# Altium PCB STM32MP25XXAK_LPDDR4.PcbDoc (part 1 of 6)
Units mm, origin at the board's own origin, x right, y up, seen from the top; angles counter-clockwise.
Board outline 120 x 79.6 mm, 4 copper layers (Top Layer, Signal Layer 1, Signal Layer 2, Bottom Layer), stack 1.614 mm thick; 190 components, 143 nets, 1208 pads, 757 vias.
Unrouted connection lines stored in the file: 3.
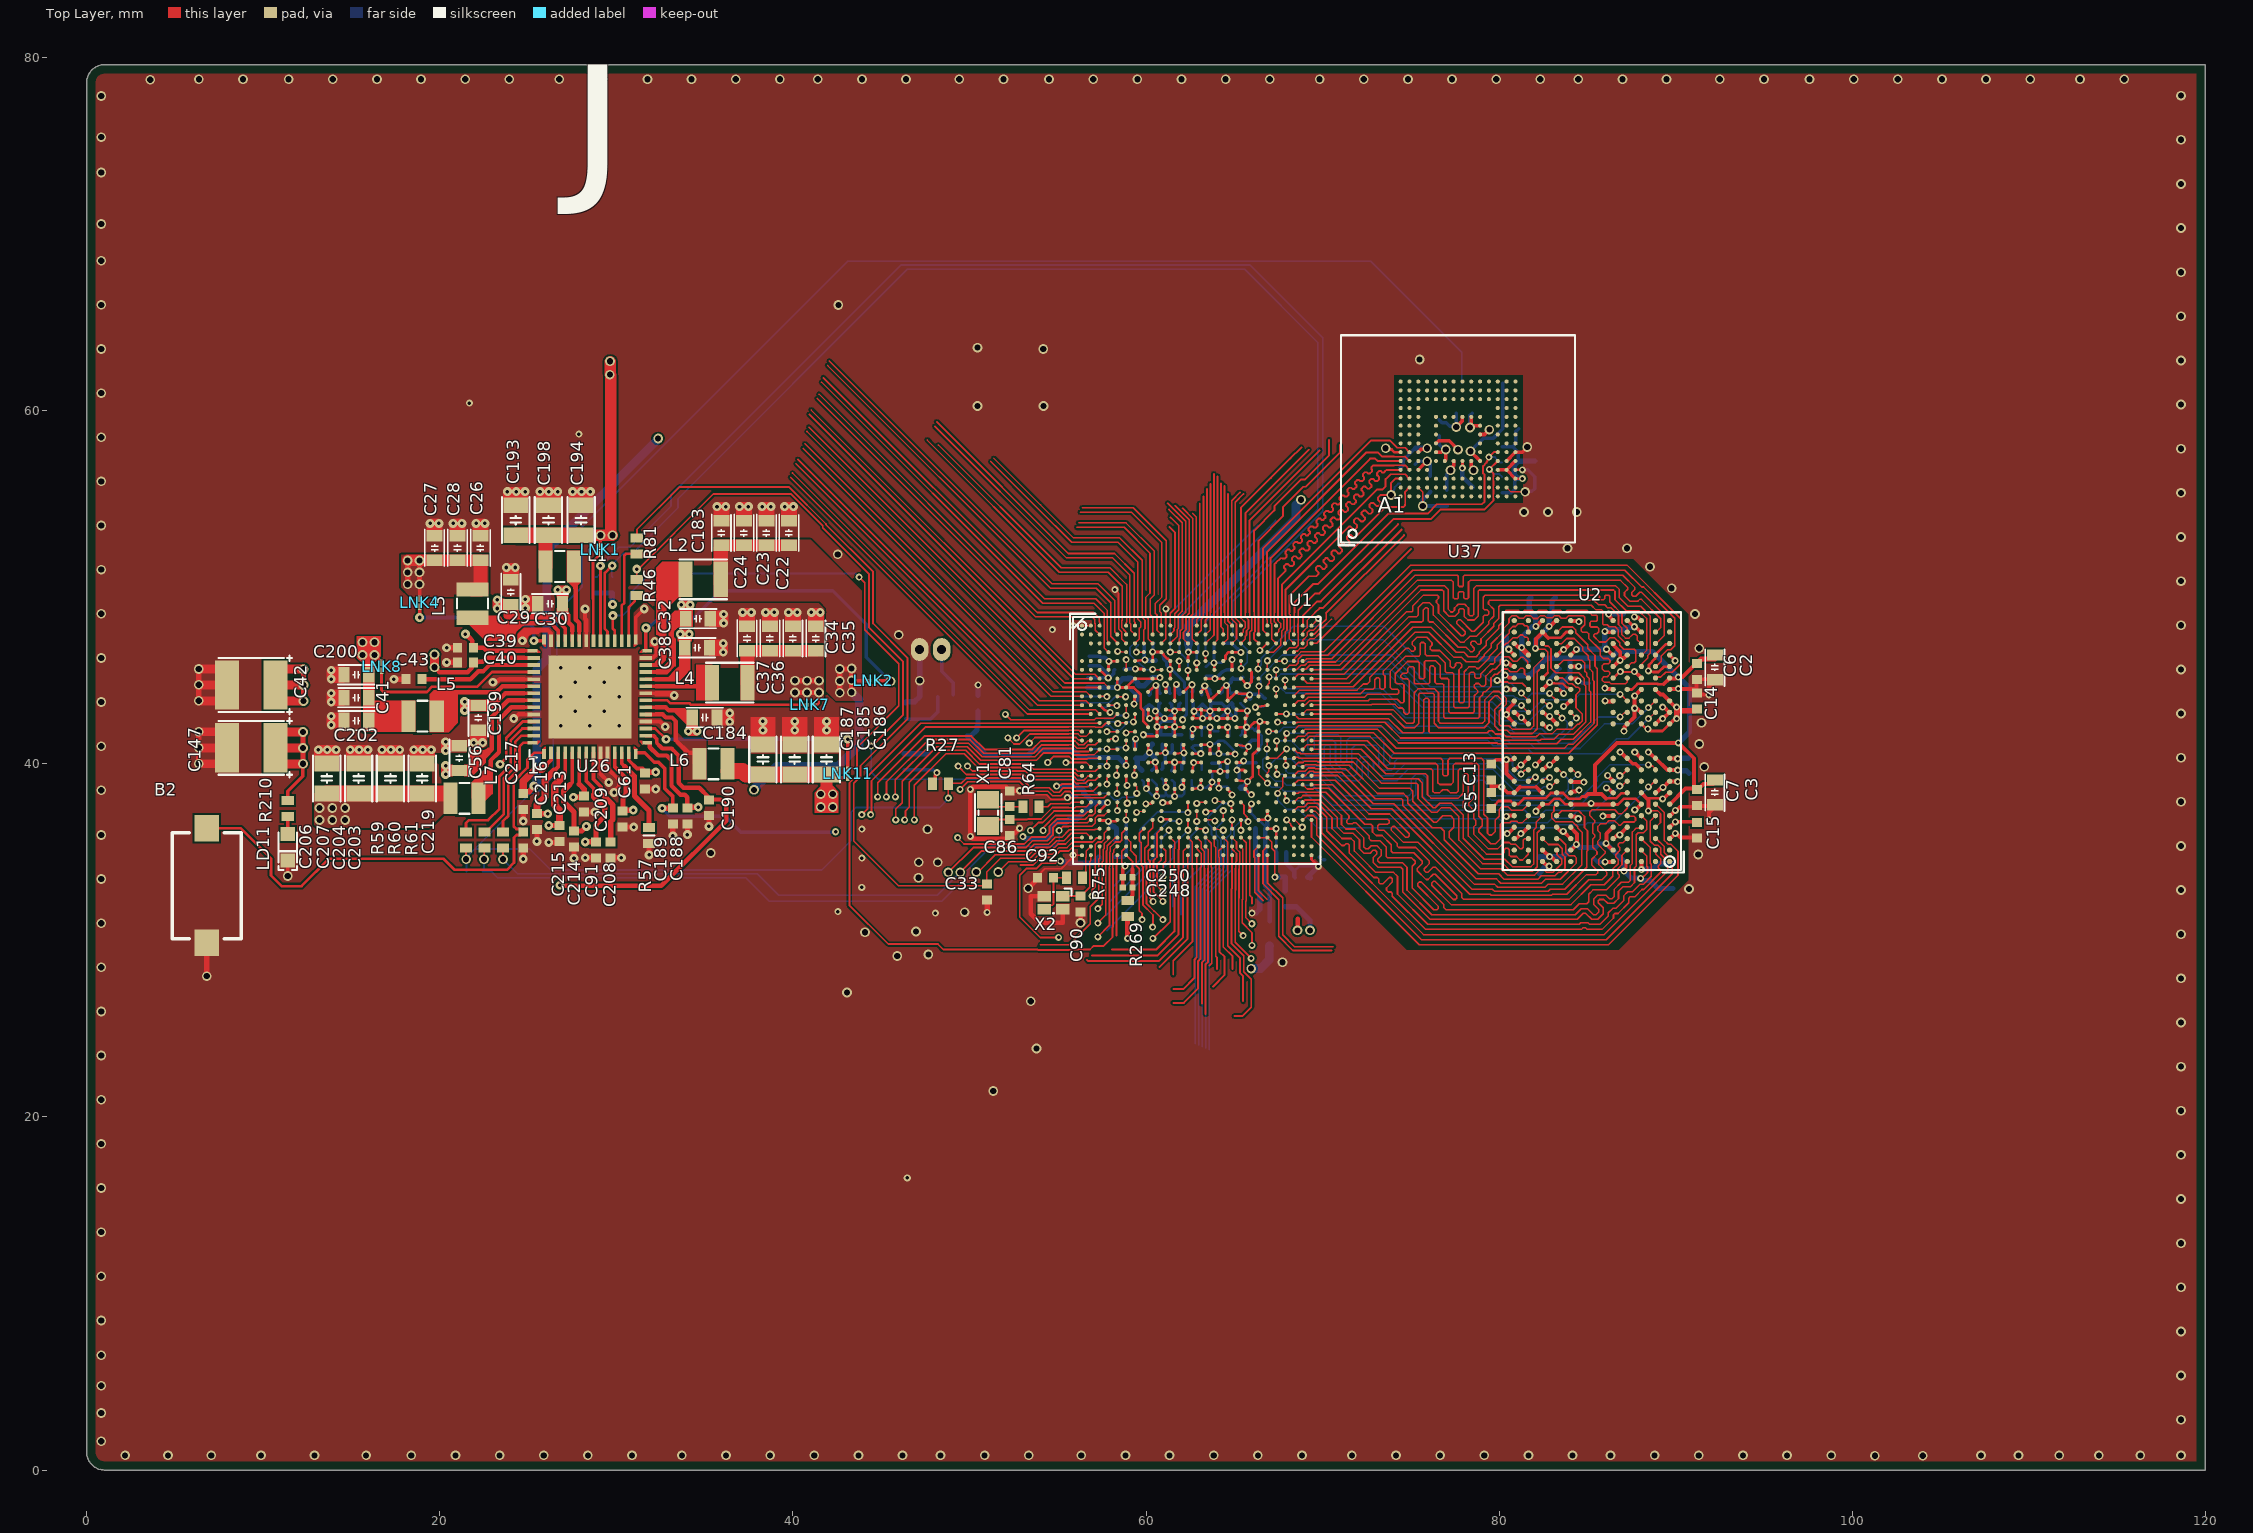
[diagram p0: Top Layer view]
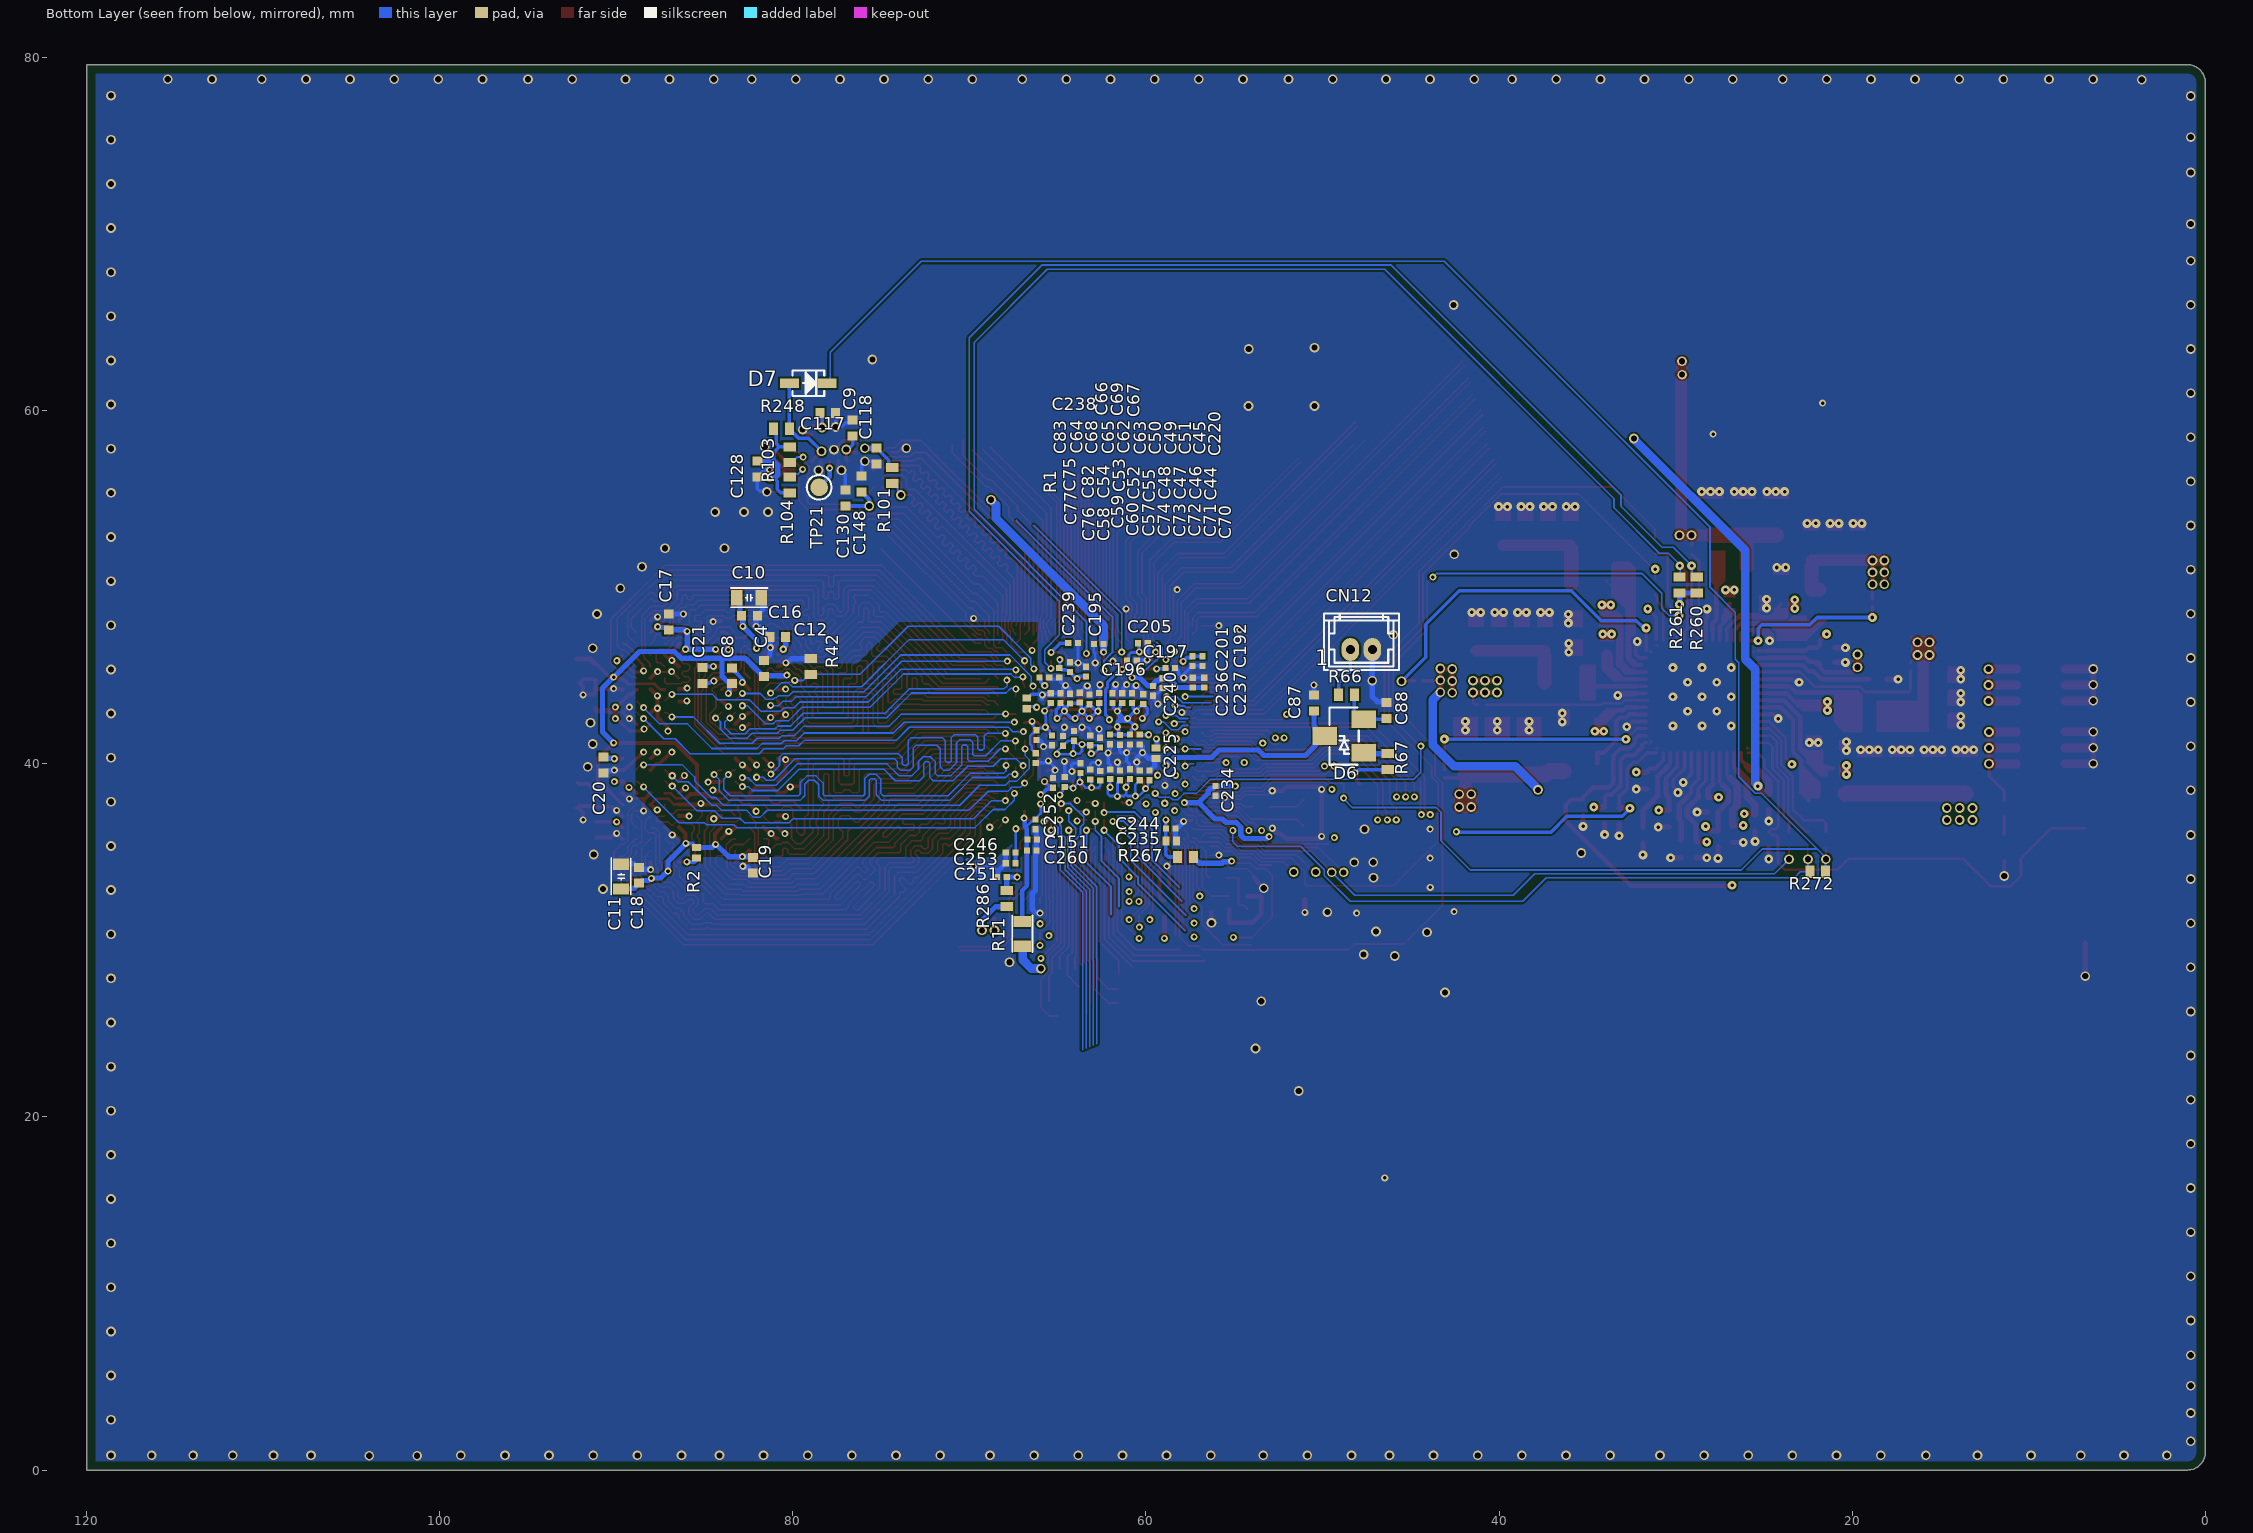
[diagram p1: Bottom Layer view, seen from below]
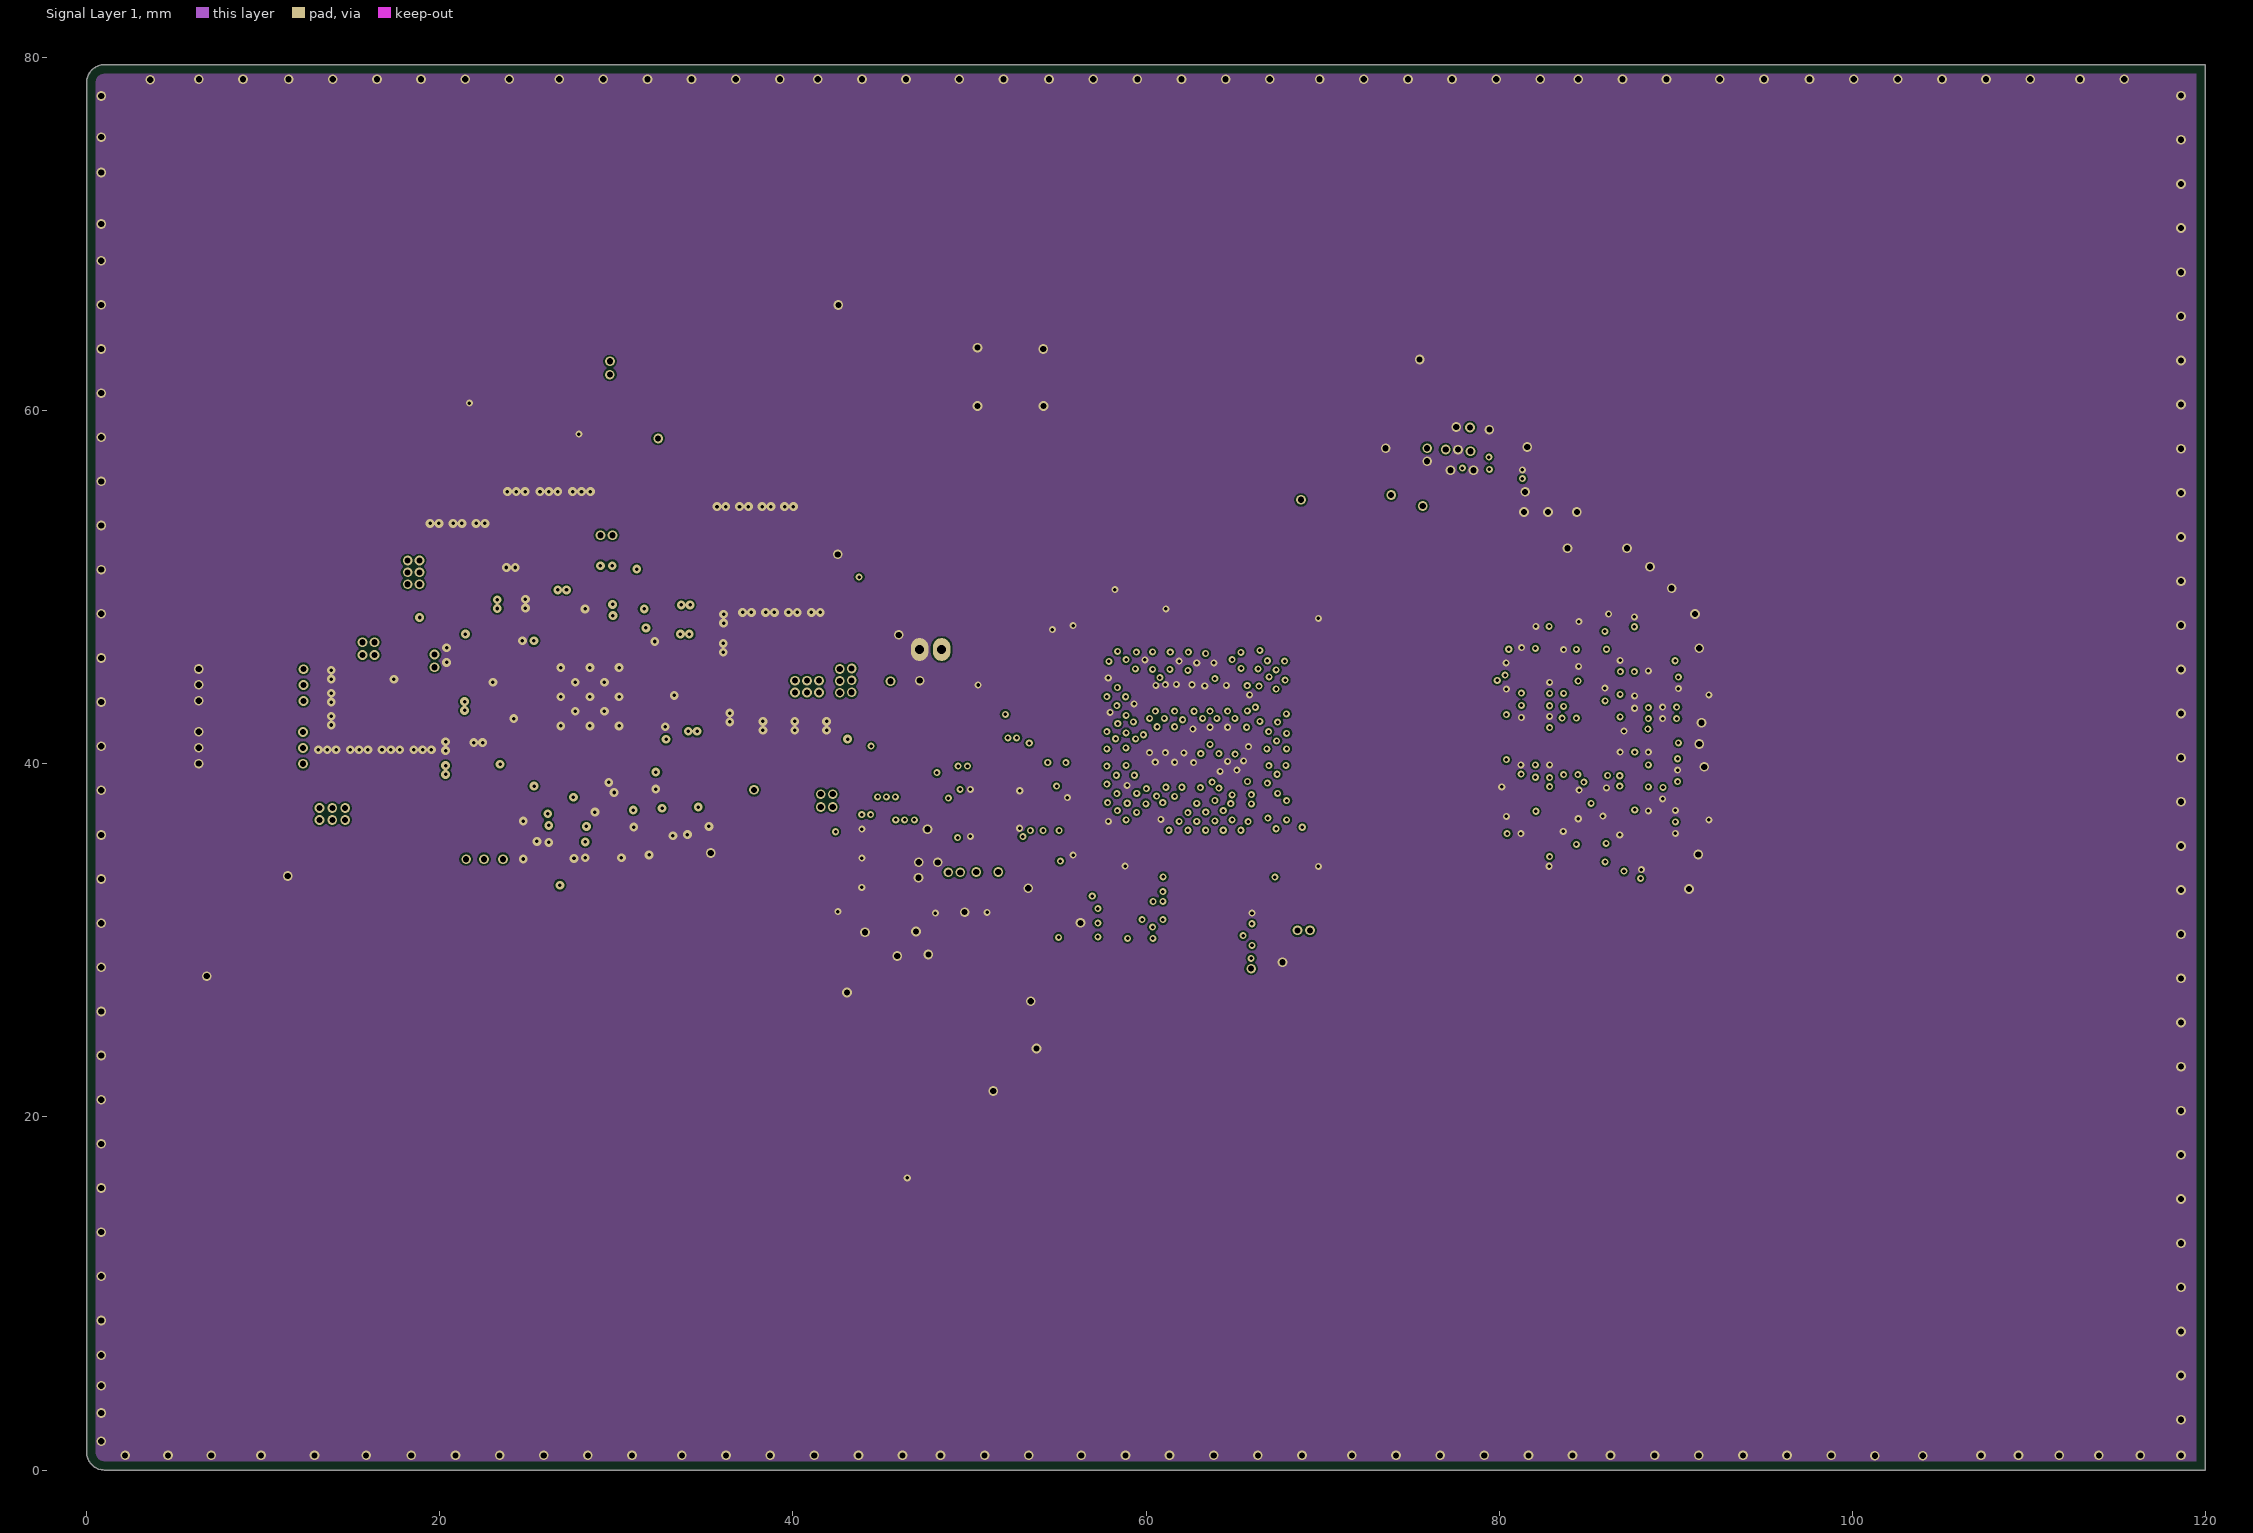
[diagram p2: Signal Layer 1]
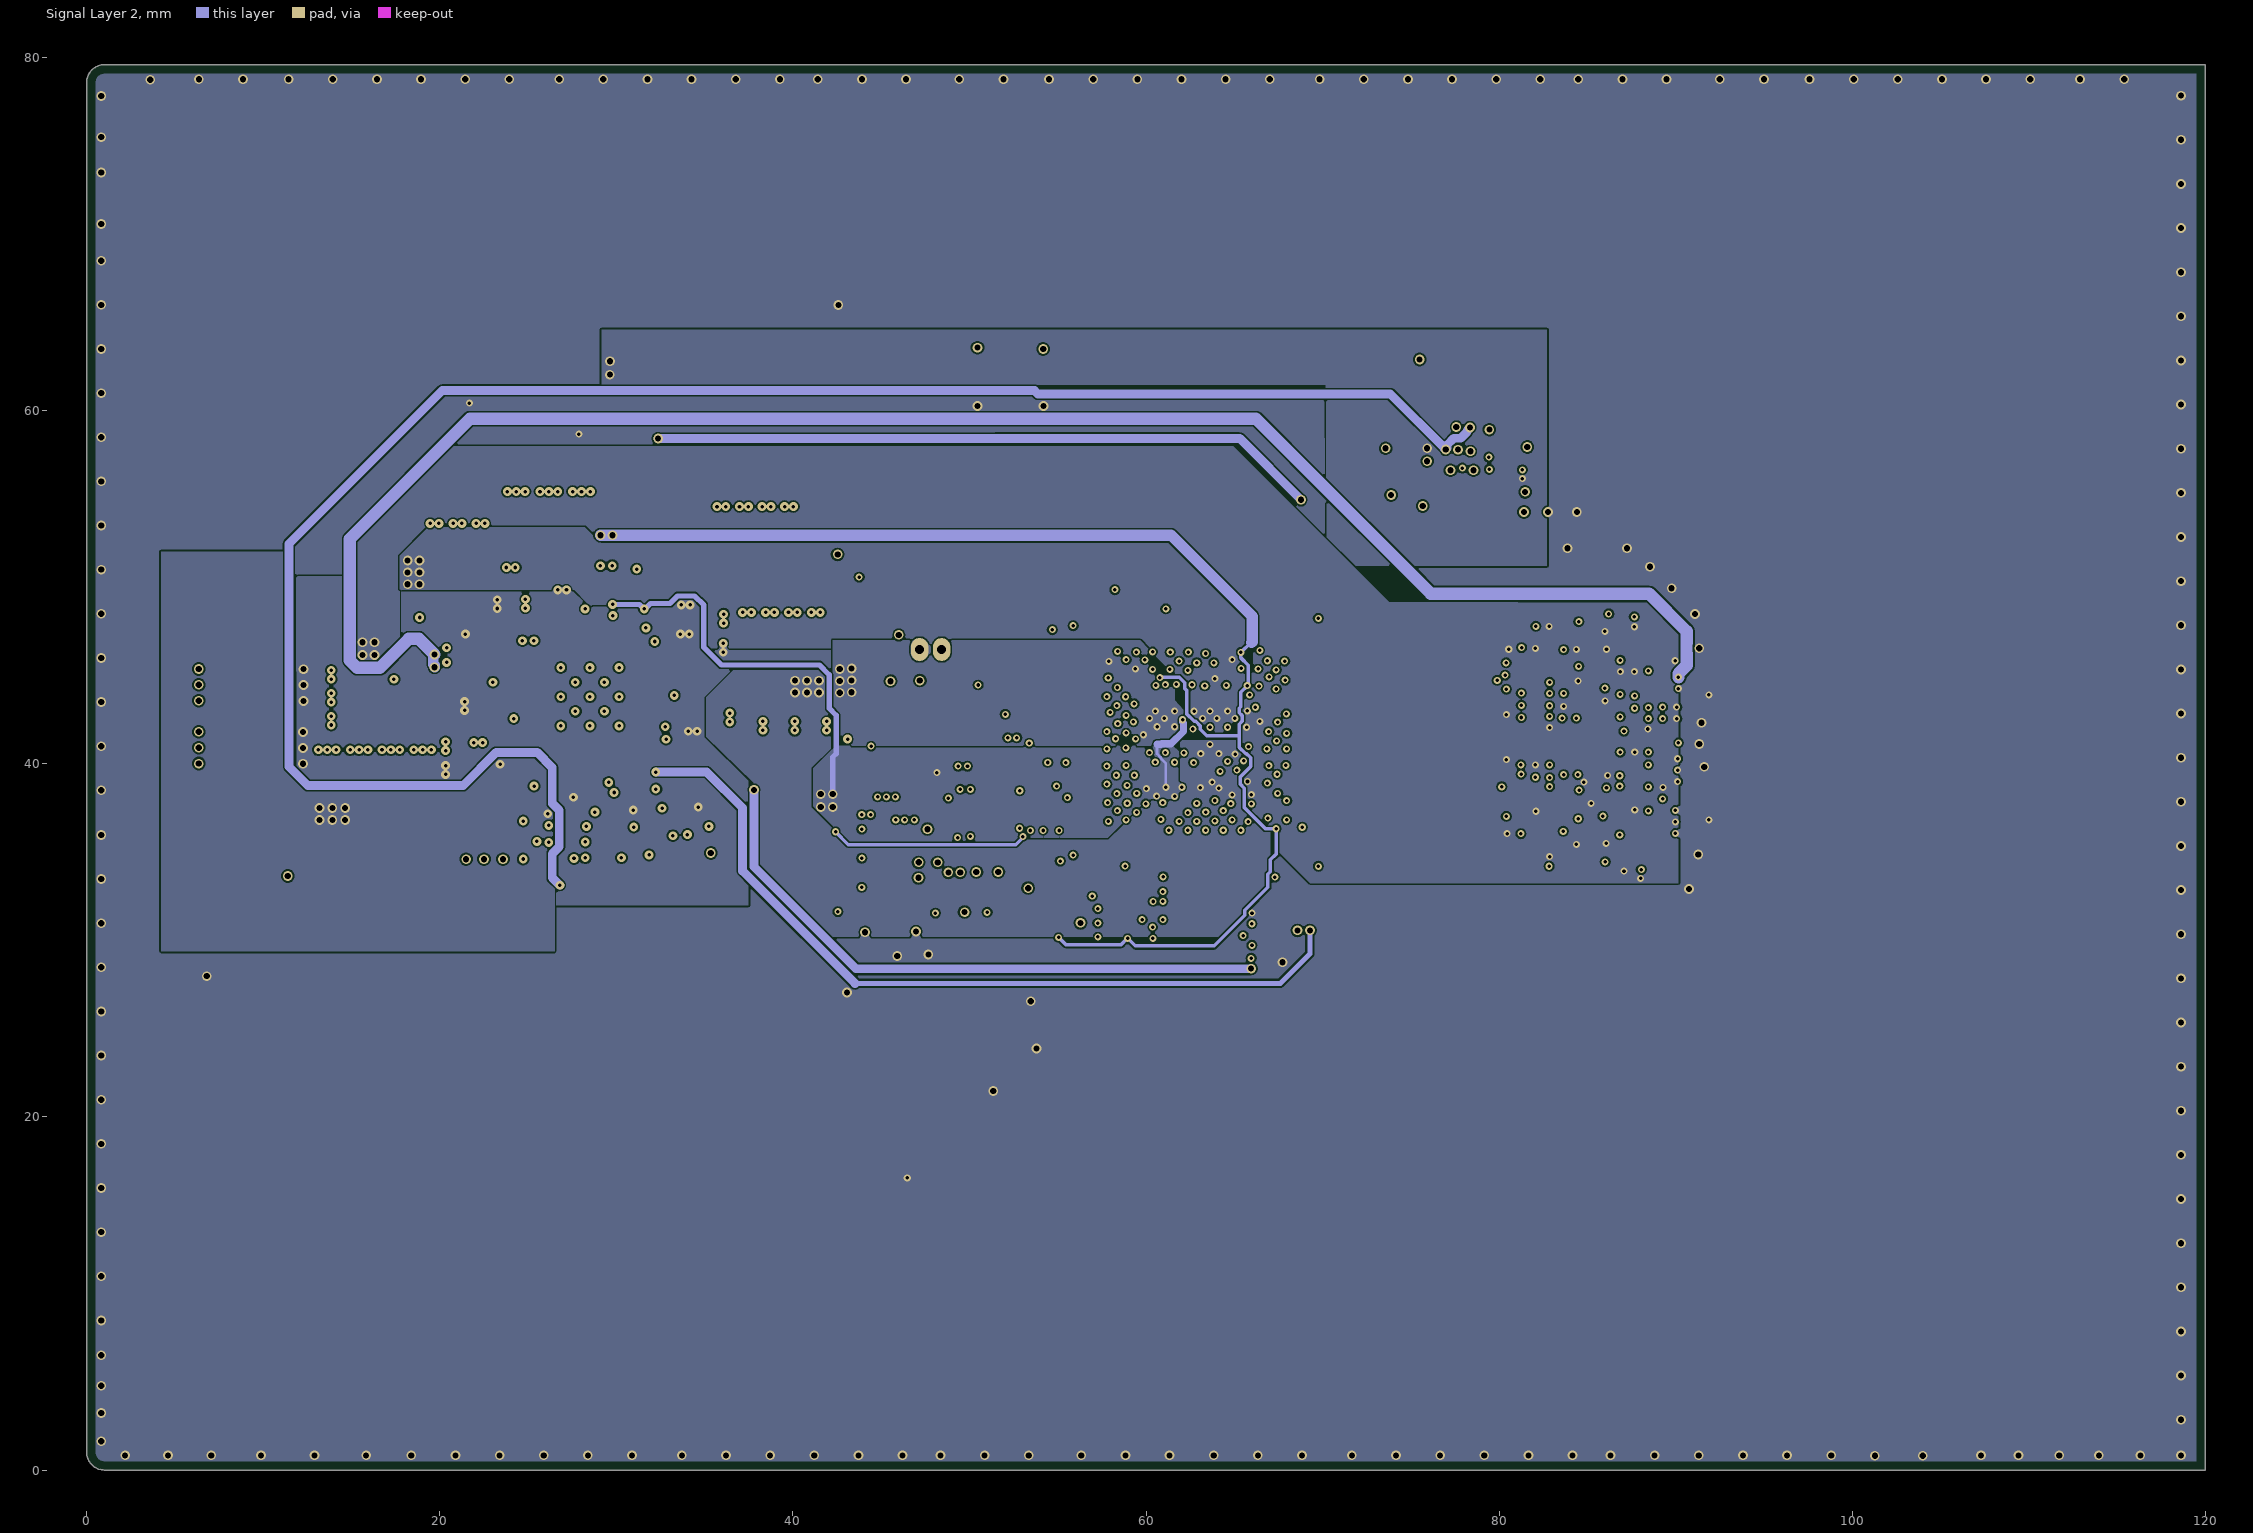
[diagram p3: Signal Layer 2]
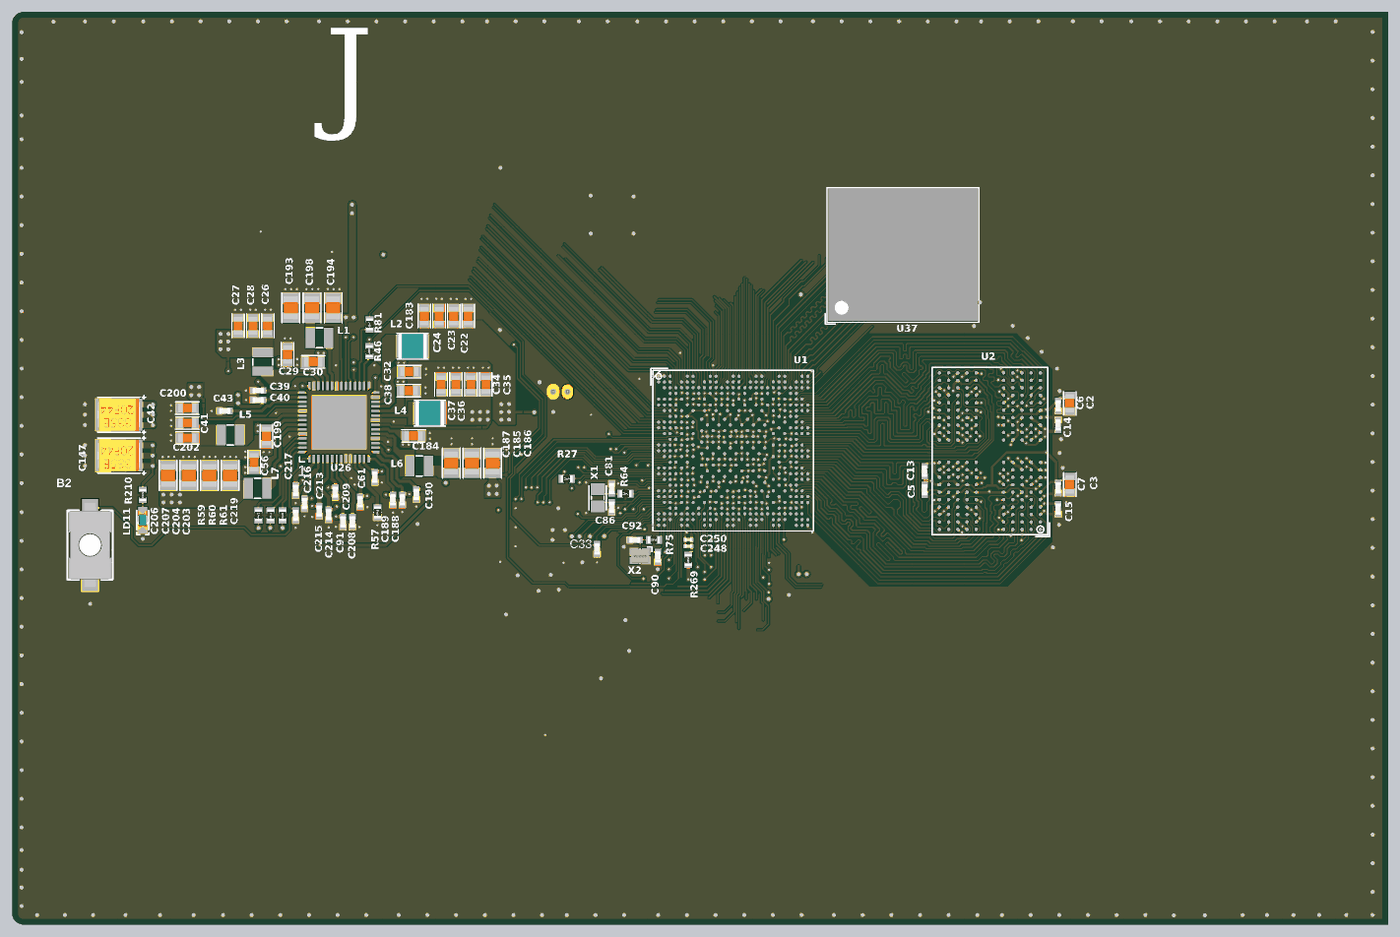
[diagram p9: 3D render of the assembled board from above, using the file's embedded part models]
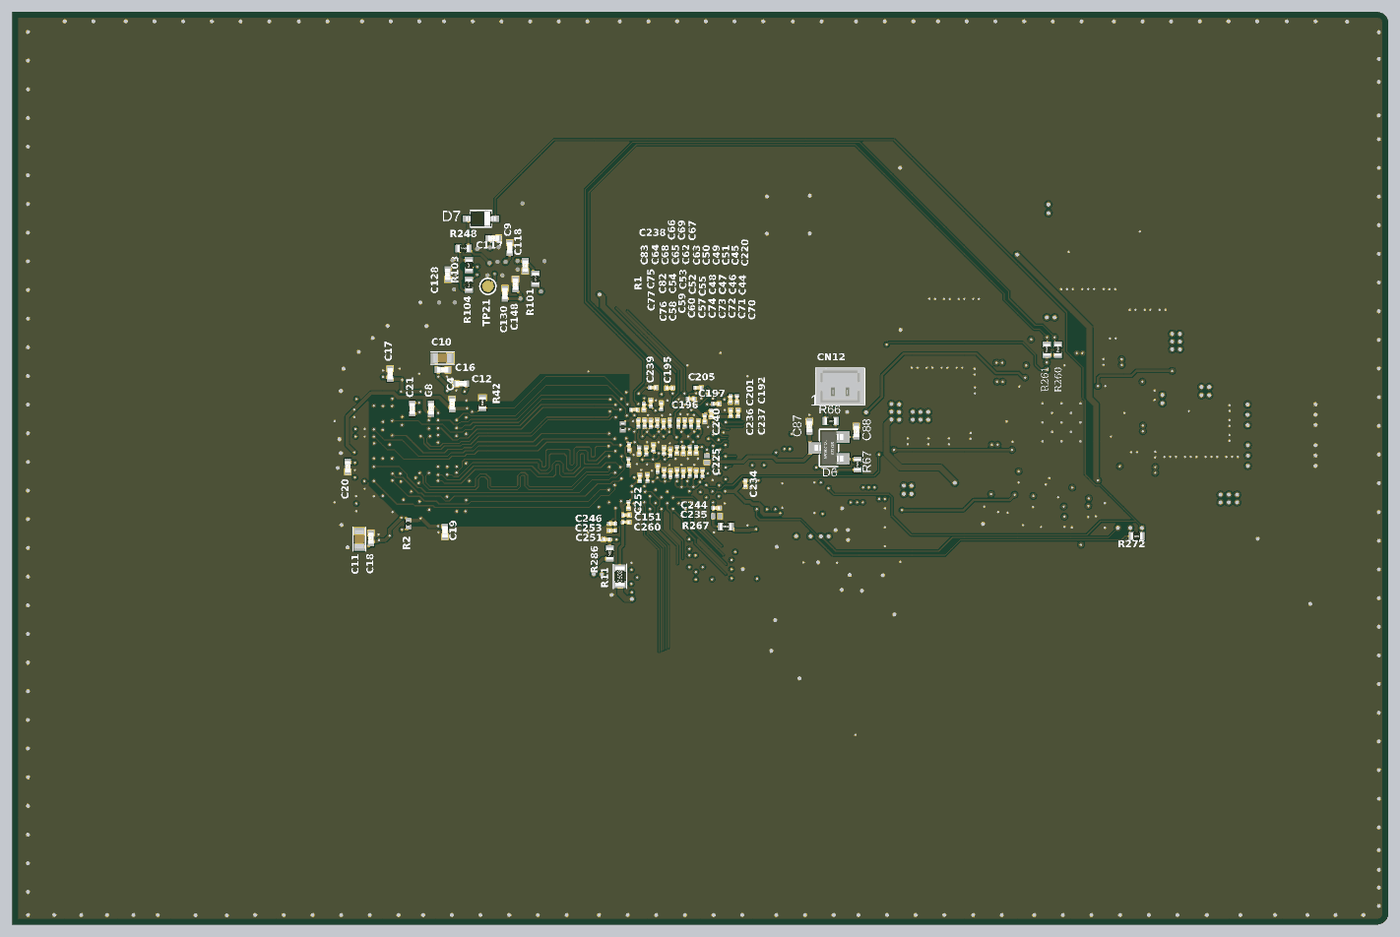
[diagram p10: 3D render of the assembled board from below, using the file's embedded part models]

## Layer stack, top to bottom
Top Solder: solder mask 0.025, Solder Resist, Dk 3.5
Top Layer: signal copper 0.037
Dielectric 1: prepreg 0.07, Dk 3.8
Signal Layer 1: signal copper 0.035
Dielectric 2: core 1.33, Dk 4.3
Signal Layer 2: signal copper 0.035
Dielectric 3: prepreg 0.07, Dk 3.8
Bottom Layer: signal copper 0.037
Bottom Solder: solder mask 0.025, Solder Resist, Dk 3.5

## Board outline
0,1 0,78.6 cw(c1,78.6) 1,79.6 120,79.6 120,0 1,0 cw(c1,1)

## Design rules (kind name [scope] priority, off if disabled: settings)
BoardOutlineClearance Silkscreen [OnLayer('Top Overlay') or OnLayer('Bottom Overlay')] p1: gap=0 ignorepadtopadclearanceinfootprint=FALSE
BoardOutlineClearance [All] p2: gap=0.5 ignorepadtopadclearanceinfootprint=FALSE
Clearance Clearance_Default [All] p1: gap=0.1 ignorepadtopadclearanceinfootprint=TRUE except(0: SMDPad-Hole Via-Hole; 0.09: Track-Track Track-SMDPad; 0.2: Arc-Hole Track-Hole THPad-Hole Fill-Hole Poly-Hole Region-Hole Text-Hole)
ComponentClearance [All] p1: gap=0.2 collisioncheckmode=3 verticalgap=0 showdistances=FALSE
DiffPairsRouting 100H [InDifferentialPairClass('100H')] p1: maxlimit=0.254 minlimit=0.16 mostfreqgap=0.16 toplayer_maxgap=0.16 toplayer_minwidth=0.09 toplayer_maxwidth=0.09 toplayer_prefwidth=0.09 midlayer1_minwidth=0.09 midlayer1_maxwidth=0.381 midlayer1_prefwidth=0.09 midlayer4_minwidth=0.09 midlayer4_maxwidth=0.381 midlayer4_prefwidth=0.09 bottomlayer_maxgap=0.16 bottomlayer_minwidth=0.09 bottomlayer_maxwidth=0.09 bottomlayer_prefwidth=0.09 impedanceprofiledriven=TRUE impedanceprofileid={628B3294-B84C-4222-8D8D-B3EA8745C43E} impedanceprofilevalue=100.000000 maxuncoupledlength=12.7
FanoutControl Fanout_BGA [IsBGA] p1: bgadir=Out bgaviamode=Closest fanoutstyle=Auto fanoutdirection=Alternating viagrid=0.025 // Fanout_BGA (Default Rule)
FanoutControl Fanout_LCC [IsLCC] p2: bgadir=Out bgaviamode=Closest fanoutstyle=Auto fanoutdirection=Alternating viagrid=0.025 // Fanout_LCC (Default Rule)
FanoutControl Fanout_SOIC [IsSOIC] p3: bgadir=Out bgaviamode=Closest fanoutstyle=Auto fanoutdirection=Alternating viagrid=0.025 // Fanout_SOIC (Default Rule)
FanoutControl Fanout_Small [(CompPinCount < 5)] p4: bgadir=Out bgaviamode=Closest fanoutstyle=Auto fanoutdirection=OutThenIn viagrid=0.025 // Fanout_Small (Default Rule)
FanoutControl Fanout_Default [All] p5: bgadir=Out bgaviamode=Closest fanoutstyle=Auto fanoutdirection=Alternating viagrid=0.025 // Fanout_Default (Default Rule)
HoleSize [All] p1: absolutevalues=TRUE maxlimit=10 minlimit=0.1 maxpercent=80.000 minpercent=20.000
HoleToHoleClearance [All] p1: gap=0.25 allowstackedmicrovias=TRUE
MinimumSolderMaskSliver MinimumSolderMaskSliver_SOLDER_BRIDGE [All vs HasFootprint('SOLDER-BRIDGE_R0603-0R')] p1: minsoldermaskwidth=0.07
MinimumSolderMaskSliver [All] p2: minsoldermaskwidth=0.075
NetAntennae [All] p1 off: netantennaetolerance=0
PlaneConnect [All] p1: planeconnectstyle=Direct reliefexpansion=0.508 reliefentries=4 reliefconductorwidth=0.21 reliefairgap=0.21
PolygonConnect PolygonConnect_Default [All] p1: connectstyle=Direct reliefconductorwidth=0.25 reliefentries=4 polygonreliefangle="90 Angle" airgapwidth=0.25
RoomDefinition RoomDefinition_eMMC [False] p1: confinementstyle=ConfineIn formatcopy=TRUE lockcomponents=FALSE outline 74.056,62.109 81.346,62.109 81.346,54.705 74.056,54.705
RoomDefinition RoomDefinition_DDR [False] p2: confinementstyle=ConfineIn formatcopy=TRUE lockcomponents=FALSE outline 79.028,49.26 90.8,49.26 90.8,33.46 79.028,33.46
RoomDefinition U_PMIC [InComponentClass('U_PMIC')] p3: confinementstyle=ConfineIn formatcopy=TRUE lockcomponents=FALSE outline 55.625,48.575 70.125,48.575 70.125,34.075 55.625,34.075
RoutingVias RoutingVias_Default [InDrillLayerPair('Top Layer - Bottom Layer')] p1: holewidth=0.15 width=0.4 viastyle="Through Hole" minholewidth=0.15 minwidth=0.4 maxholewidth=0.35 maxwidth=0.6 useviatemplates=TRUE viatemplateguid#1={8082EAB8-D593-4669-9C8E-234CD125C595} viatemplateguid#2={6F43EA8F-9356-47F3-9E64-8437B01C3073} viatemplateguid#3={0C56A9B8-CF93-463B-97D5-BDCC265789B0} viatemplateguid#4={9F28DA9E-6088-4B56-A5CF-E6C86A3E97F7} viatemplatename#1=v40h20m0mx0 viatemplatename#2=v40h20m25 viatemplatename#3=v50h20m25 viatemplatename#4=v55h35m40mx40
SilkToSilkClearance [All] p1: silktosilkclearance=0.2
SilkToSolderMaskClearance [IsPad] p1: minsilkscreentomaskgap=0.015 clearancetoexposedcopper=TRUE
SolderMaskExpansion [All] p1: expansion=0.1 istentingtop=FALSE
UnRoutedNet [All] p1 off:
ViasUnderSMD [InPadClass('PC_VIAS-IN-PAD_OK')] p1: allowed=TRUE
Width Width_SINGLE_50R [InNetClass('50H')] p1 off: maxlimit=0.199 minlimit=0.078 preferedwidth=0.199 toplayer_minwidth=0.09 toplayer_maxwidth=0.11 toplayer_prefwidth=0.11 bottomlayer_minwidth=0.11 bottomlayer_maxwidth=0.11 bottomlayer_prefwidth=0.11 impedanceprofiledriven=TRUE impedanceprofileid={152E730A-FDA4-4006-BF82-0EE0D5C1A339} impedanceprofilevalue=50.000000 minimp=50.000000 maximp=50.000000 favimp=50.000000
Width Width_SINGLE_DDR_55R [InNetClass('55H')] p2 off: maxlimit=0.199 minlimit=0.078 preferedwidth=0.199 toplayer_minwidth=0.09 toplayer_maxwidth=0.09 toplayer_prefwidth=0.09 bottomlayer_minwidth=0.09 bottomlayer_maxwidth=0.09 bottomlayer_prefwidth=0.09 impedanceprofiledriven=TRUE impedanceprofileid={D5948A69-504E-4D29-B9E5-77B49DDD78E4} impedanceprofilevalue=55.000000 minimp=50.000000 maximp=50.000000 favimp=50.000000
Width Width_Default [InNet('GND')] p3: maxlimit=10 minlimit=0.09 preferedwidth=0.3 toplayer_prefwidth=0.09 bottomlayer_prefwidth=0.09 minimp=50.000000 maximp=50.000000 favimp=50.000000
15 further rules are at their usual default settings.

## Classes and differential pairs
net class 100H: DDR_CLK_A_N DDR_CLK_A_P DDR_CLK_B_N DDR_CLK_B_P DDR_DQS0_A_N DDR_DQS0_A_P DDR_DQS0_B_N DDR_DQS0_B_P DDR_DQS1_A_N DDR_DQS1_A_P DDR_DQS1_B_N DDR_DQS1_B_P
differential pair class 100H: CLKA CLKB DQS0A DQS0B DQS1A DQS1B
net class eMMC.SDMMC2_D[0..7]: eMMC.SDMMC2_CK eMMC.SDMMC2_CMD eMMC.SDMMC2_D0 eMMC.SDMMC2_D1 eMMC.SDMMC2_D2 eMMC.SDMMC2_D3 eMMC.SDMMC2_D4 eMMC.SDMMC2_D5 eMMC.SDMMC2_D6 eMMC.SDMMC2_D7
component class U_eMMC: C9 C117 C118 C128 C130 C148 D7 R101 R103 R104 R248 TP21 U37
component class "U_STM32MP25XXAK I_Os": C33 C81 C86 C90 C92 R27 R64 R75 R260 R261 R272 U1 X1 X2
component class "U_STM32MP25XXAK Power": C44 C45 C46 C47 C48 C49 C50 C51 C52 C53 C54 C55 C57 C58 C59 C60 C62 C63 C64 C65 C66 C67 C68 C69 C70 C71 C72 C73 C74 C75 C76 C77 C82 C83 C87 C88 C151 C192 C195 C196 C197 C201 C205 C220 C225 C234 C235 C236 C237 C238 C239 C240 C244 C246 C248 C250 C251 C252 C253 C260 CN12 D6 R11 R66 R67 R267 R269 R286
component class U_PMIC: B2 C22 C23 C24 C26 C27 C28 C29 C30 C32 C34 C35 C36 C37 C38 C39 C40 C41 C42 C43 C56 C61 C91 C147 C183 C184 C185 C186 C187 C188 C189 C190 C193 C194 C198 C199 C200 C202 C203 C204 C206 C207 C208 C209 C213 C214 C215 C216 C217 C219 L1 L2 L3 L4 L5 L6 L7 LD11 LNK1 LNK2 LNK4 LNK7 LNK8 LNK11 R46 R57 R59 R60 R61 R81 R210 U26
differential pair CLKB: +DDR_CLK_B_P -DDR_CLK_B_N
differential pair CLKA: +DDR_CLK_A_P -DDR_CLK_A_N
differential pair DQS1B: +DDR_DQS1_B_P -DDR_DQS1_B_N
differential pair DQS0B: +DDR_DQS0_B_P -DDR_DQS0_B_N
differential pair DQS1A: +DDR_DQS1_A_P -DDR_DQS1_A_N
differential pair DQS0A: +DDR_DQS0_A_P -DDR_DQS0_A_N

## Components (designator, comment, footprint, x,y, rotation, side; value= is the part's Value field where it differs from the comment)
B2 "SW_PUSH_SMD_2P" SWI_WE_434121025816 6.795,33.104 r90 top value=434121025816
C2 "Capacitor" C0603 92.225,45.46 r90 top value=10uF
C3 "Capacitor" C0603 92.225,38.385 r90 top value=10uF
C4 "100nF" C0402 81.63,45.397 r90 bottom
C5 "100nF" C0402 79.559,37.929 r90 top
C6 "100nF" C0402 91.209,45.24 r270 top
C7 "100nF" C0402 91.209,38.09 r270 top
C8 "100nF" C0402 83.461,44.99 r90 bottom
C9 "Capacitor" C0402 76.615,59.03 r270 bottom value=100nF
C10 "Capacitor" C0603 82.486,49.415 r0 bottom value=10uF
C11 "Capacitor" C0603 89.736,33.615 r270 bottom value=10uF
C12 "100nF" C0402 80.861,47.18 r0 bottom
C13 "100nF" C0402 79.559,39.529 r270 top
C14 "100nF" C0402 91.209,43.565 r90 top
C15 "100nF" C0402 91.209,36.24 r270 top
C16 "100nF" C0402 82.461,48.39 r180 bottom
C17 "100nF" C0402 87.036,48.04 r90 bottom
C18 "100nF" C0402 88.711,33.69 r90 bottom
C19 "100nF" C0402 82.261,34.255 r270 bottom
C20 "100nF" C0402 90.736,39.94 r270 bottom
C21 "100nF" C0402 85.111,45.015 r90 bottom
C22 "Capacitor" C0603 39.775,53.075 r270 top value=22uF
C23 "Capacitor" C0603 38.5,53.075 r270 top value=22uF
C24 "Capacitor" C0603 37.225,53.075 r270 top value=22uF
C26 "Capacitor" C0603 22.3,52.225 r270 top value=22uF
C27 "Capacitor" C0603 19.7,52.225 r270 top value=22uF
C28 "Capacitor" C0603 21,52.225 r270 top value=22uF
C29 "Capacitor" C0603 24.025,49.725 r270 top value=10uF
C30 "Capacitor" C0603 26.25,49.075 r0 top value=10uF
C32 "Capacitor" C0603 34.625,48.225 r180 top value=10uF
C33 "Capacitor" C0402 51,32.75 r90 top value=10nF
C34 "Capacitor" C0603 40,47.1 r270 top value=22uF
C35 "Capacitor" C0603 41.3,47.1 r270 top value=22uF
C36 "Capacitor" C0603 38.7,47.1 r270 top value=22uF
C37 "Capacitor" C0603 37.4,47.1 r270 top value=22uF
C38 "Capacitor" C0603 34.575,46.575 r180 top value=10uF
C39 "Capacitor" C0402 21.445,46.575 r0 top value=1uF
C40 "Capacitor" C0402 21.445,45.75 r0 top value=10uF
C41 "Capacitor" C0603 15.275,43.75 r0 top value=22uF
C42 "Cap_POL_TANA" CPOL_TCJ-B_1210_H210 9.311,44.468 r180 top value=100uF
C43 "Capacitor" C0402 18.535,44.8 r0 top value=1uF
C44 "1uF" C0201_MURATA_GRM033_H0P3 60.351,41.38 r270 bottom
C45 "1uF" C0201_MURATA_GRM033_H0P3 60.16,43.67 r270 bottom
C46 "1uF" C0201_MURATA_GRM033_H0P3 60.915,41.38 r90 bottom
C47 "1uF" C0201_MURATA_GRM033_H0P3 61.476,41.356 r270 bottom
C48 "1uF" C0201_MURATA_GRM033_H0P3 62.038,41.382 r90 bottom
C49 "1uF" C0201_MURATA_GRM033_H0P3 61.35,43.725 r270 bottom
C50 "1uF" C0201_MURATA_GRM033_H0P3 61.9,43.725 r270 bottom
C51 "1uF" C0201_MURATA_GRM033_H0P3 60.8,43.725 r270 bottom
C52 "1uF" C0201_MURATA_GRM033_H0P3 63.162,41.332 r270 bottom
C53 "1uF" C0201_MURATA_GRM033_H0P3 64.083,41.581 r270 bottom
C54 "1uF" C0201_MURATA_GRM033_H0P3 64.706,41.304 r270 bottom
C55 "1uF" C0201_MURATA_GRM033_H0P3 62.6,41.2 r270 bottom
C56 "Capacitor" C0603 21.1,40.325 r270 top value=10uF
C57 "1uF" C0201_MURATA_GRM033_H0P3 62.592,39.328 r270 bottom
C58 "1uF" C0201_MURATA_GRM033_H0P3 64.607,38.972 r270 bottom
C59 "1uF" C0201_MURATA_GRM033_H0P3 63.714,39.761 r270 bottom
C60 "1uF" C0201_MURATA_GRM033_H0P3 63.154,39.397 r270 bottom
C61 "Capacitor" C0402 31.625,39.02 r90 top value=4.7uF
C62 "1uF" C0201_MURATA_GRM033_H0P3 63.2,43.65 r90 bottom
C63 "1uF" C0201_MURATA_GRM033_H0P3 62.65,43.73 r270 bottom
C64 "1uF" C0201_MURATA_GRM033_H0P3 64.85,43.725 r270 bottom
C65 "1uF" C0201_MURATA_GRM033_H0P3 63.75,43.75 r90 bottom
C66 "1uF" C0201_MURATA_GRM033_H0P3 64.915,45.16 r90 bottom
C67 "1uF" C0201_MURATA_GRM033_H0P3 63.4,45.225 r270 bottom
C68 "1uF" C0201_MURATA_GRM033_H0P3 64.3,43.7 r270 bottom
C69 "1uF" C0201_MURATA_GRM033_H0P3 64.305,45.477 r270 bottom
C70 "1uF" C0201_MURATA_GRM033_H0P3 59.805,39.35 r90 bottom
C71 "1uF" C0201_MURATA_GRM033_H0P3 60.355,39.35 r270 bottom
C72 "1uF" C0201_MURATA_GRM033_H0P3 60.905,39.423 r270 bottom
C73 "1uF" C0201_MURATA_GRM033_H0P3 61.467,39.349 r90 bottom
C74 "1uF" C0201_MURATA_GRM033_H0P3 62.03,39.408 r270 bottom
C75 "1uF" C0201_MURATA_GRM033_H0P3 66.205,41.625 r90 bottom
C76 "1uF" C0201_MURATA_GRM033_H0P3 65.274,38.923 r270 bottom
C77 "1uF" C0201_MURATA_GRM033_H0P3 66.25,40.325 r270 bottom
C81 "Capacitor" C0402 52.285,38.025 r90 top value=6.8pF
C82 "1uF" C0201_MURATA_GRM033_H0P3 65.325,41.325 r90 bottom
C83 "1uF" C0201_MURATA_GRM033_H0P3 65.395,43.725 r270 bottom
C86 "Capacitor" C0402 52.285,36.4 r270 top value=6.8pF
C87 "" C0402 50.485,43.438 r270 bottom value=100nF
C88 "Capacitor" C0402 46.382,43.015 r270 bottom value=2.2uF
C90 "Capacitor" C0402 56.293,32.06 r90 top value=6.8pF
C91 "Capacitor" C0402 28.85,35.13 r270 top value=4.7uF
C92 "Capacitor" C0402 54.309,33.546 r180 top value=6.8pF
C117 "Capacitor" C0402 78.025,59.864 r0 bottom value=2.2uF
C118 "Capacitor" C0402 75.26,57.43 r90 bottom value=100nF
C128 "Capacitor" C0402 82.015,56.705 r90 bottom value=2.2uF
C130 "Capacitor" C0402 77.027,55.055 r270 bottom value=100nF
C147 "Cap_POL_TANA" CPOL_TCJ-B_1210_H210 9.311,40.906 r180 top value=100uF
C148 "Capacitor" C0402 76.11,55.855 r270 bottom value=2.2uF
C151 "Capacitor" C0201_MURATA_GRM033_H0P3 66.446,35.716 r0 bottom value=1uF
C183 "Capacitor" C0603 35.95,53.075 r270 top value=22uF
C184 "Capacitor" C0603 34.997,42.625 r180 top value=10uF
C185 "Capacitor" C0805 40.1,40.25 r270 top value=22uF
C186 "Capacitor" C0805 41.9,40.25 r270 top value=22uF
C187 "Capacitor" C0805 38.3,40.25 r270 top value=22uF
C188 "Capacitor" C0402 34.025,37.04 r90 top value=1uF
C189 "Capacitor" C0402 33.2,37.04 r90 top value=4.7uF
C190 "Capacitor" C0402 35.25,37.515 r270 top value=4.7uF
C192 "Capacitor" C0201_MURATA_GRM033_H0P3 56.8,45.825 r90 bottom value=100nF
C193 "Capacitor" C0805 24.3,53.8 r270 top value=22uF
C194 "Capacitor" C0805 28,53.8 r270 top value=22uF
C195 "Capacitor" C0201_MURATA_GRM033_H0P3 62.675,46.787 r180 bottom value=100nF
C196 "Capacitor" C0201_MURATA_GRM033_H0P3 60.8,45.85 r0 bottom value=100nF
C197 "Capacitor" C0201_MURATA_GRM033_H0P3 58.625,45.425 r0 bottom value=100nF
C198 "Capacitor" C0805 26.15,53.8 r270 top value=22uF
C199 "Capacitor" C0603 22.175,42.6 r90 top value=10uF
C200 "Capacitor" C0603 15.275,45.05 r0 top value=22uF
C201 "Capacitor" C0201_MURATA_GRM033_H0P3 57.375,45.825 r90 bottom value=100nF
C202 "Capacitor" C0603 15.275,42.45 r0 top value=22uF
C203 "Capacitor" C0805 19,39.173 r270 top value=22uF
C204 "Capacitor" C0805 17.2,39.173 r270 top value=22uF
C205 "Capacitor" C0201_MURATA_GRM033_H0P3 60.177,46.829 r0 bottom value=100nF
C206 "Capacitor" C0805 13.6,39.173 r270 top value=22uF
C207 "Capacitor" C0805 15.4,39.173 r270 top value=22uF
C208 "Capacitor" C0402 29.675,35.13 r270 top value=4.7uF
C209 "Capacitor" C0402 30.35,36.87 r90 top value=4.7uF
C213 "Capacitor" C0402 28.175,37.72 r90 top value=1uF
C214 "Capacitor" C0402 27.6,35.75 r270 top value=4.7uF
C215 "Capacitor" C0402 26.775,36.06 r270 top value=4.7uF
C216 "Capacitor" C0402 25.5,36.725 r90 top value=1uF
C217 "Capacitor" C0402 24.725,37.87 r270 top value=4.7uF
C219 "Capacitor" C0402 24.727,35.695 r90 top value=10nF
C220 "Capacitor" C0201_MURATA_GRM033_H0P3 59.609,44.131 r90 bottom value=100nF
C225 "Capacitor" C0201_H0P5 59.425,40.6 r90 bottom value=4.7uF
C234 "Capacitor" C0201_MURATA_GRM033_H0P3 56.064,38.473 r90 bottom value=100nF
C235 "Capacitor" C0201_H0P5 58.575,35.625 r0 bottom value=2.2uF
C236 "Capacitor" C0201_MURATA_GRM033_H0P3 57.35,44.6 r270 bottom value=100nF
C237 "Capacitor" C0201_MURATA_GRM033_H0P3 56.696,44.605 r270 bottom value=100nF
C238 "Capacitor" C0201_MURATA_GRM033_H0P3 65.758,44.894 r0 bottom value=100nF
C239 "Capacitor" C0201_MURATA_GRM033_H0P3 64.125,46.837 r0 bottom value=100nF
C240 "Capacitor" C0201_MURATA_GRM033_H0P3 59.05,44.575 r90 bottom value=100nF
C244 "Capacitor" C0201_MURATA_GRM033_H0P3 58.6,36.331 r0 bottom value=100nF
C246 "Capacitor" C0201_MURATA_GRM033_H0P3 67.666,34.986 r180 bottom value=100nF
C248 "Capacitor" C0201_MURATA_GRM033_H0P3 58.958,33.002 r0 top value=100nF
C250 "Capacitor" C0201_MURATA_GRM033_H0P3 58.958,33.572 r0 top value=1uF
C251 "Capacitor" C0201_MURATA_GRM033_H0P3 68.165,33.588 r180 bottom value=100nF
C252 "Capacitor" C0201_MURATA_GRM033_H0P3 66.255,36.575 r90 bottom value=1uF
C253 "Capacitor" C0201_MURATA_GRM033_H0P3 67.666,34.367 r180 bottom value=100nF
C260 "Capacitor" C0201_MURATA_GRM033_H0P3 66.473,35.094 r0 bottom value=1uF
CN12 "" CON_MOLEX_53047-0210 47.8,46.475 r180 bottom value="Header 2x1"
D6 "DIODE_3P_DUAL_COMMON_CATHODE" DIO_SOT23 48.773,41.573 r90 bottom value=BAT54CFILM
D7 "BAT60JFILM" DIO_SOD323 79.125,61.563 r180 bottom
L1 "Inductor" IND_2016_MURATA_LQM2MPN2R2NG0 26.795,51.175 r180 top value=2.2uH
L2 "Inductor" IND_2520_TOKO_DFE252012P 34.915,50.45 r0 top value=0.68µH
L3 "Inductor" IND_2016_MURATA_LQM2MPN2R2NG0 21.85,49.075 r90 top value=0.68uH
L4 "Inductor" IND_2520_TOKO_DFE252012P 36.425,44.6 r0 top value=0.68µH
L5 "Inductor" IND_2016_MURATA_LQM2MPN2R2NG0 19.025,42.7 r180 top value=0.68uH
L6 "Inductor" IND_2016_MURATA_LQM2MPN2R2NG0 35.5,40 r0 top value=2.2uH
L7 "Inductor" IND_2016_MURATA_LQM2MPN2R2NG0 21.4,38.05 r180 top value=0.68uH
LD11 "LED_green" LED_0603_OSRAM_LG-Q396-PS-35_GREEN_1A2K_H0P4 11.386,35.272 r270 top value=GREEN
LNK1 "link_200" LINK200 29.1,52.123 r0 top
LNK2 "link_200" LINK200 44.541,44.7 r90 top
LNK4 "link_200" LINK200 18.85,49.125 r180 top
LNK7 "link_200" LINK200 40.95,43.35 r270 top
LNK8 "link_200" LINK200 16.7,45.498 r0 top
LNK11 "link_200" LINK200 43.1,39.44 r180 top
R1 "Resistor" R0201_H0P23 66.751,43.42 r270 bottom value=240R
R2 "Resistor" R0201_H0P23 85.461,34.965 r90 bottom value=240R
R11 "Resistor" R0603 67,30.375 r90 bottom value=0R
R27 "Resistor" R0402 48.355,38.872 r180 top value=10K
R42 "Resistor" R0402 78.986,45.505 r270 bottom value=10K
R46 "" R0402 31.15,49.998 r270 top value=0R
R57 "" R0402 31.85,35.95 r90 top value=0R
R59 "" R0402 21.48,35.695 r90 top value=0R
R60 "" R0402 22.53,35.695 r90 top value=0R
R61 "" R0402 23.58,35.695 r90 top value=0R
R64 "" R0402 53.485,37.575 r180 top value=0R
R66 "Resistor" R0402 48.633,43.917 r180 bottom value=20R
R67 "Resistor" R0402 46.3,40.125 r270 bottom value=0R
R75 "" R0402 55.959,33.546 r0 top value=0R
R81 "" R0402 31.163,52.348 r270 top value=0R
R101 "Resistor" R0402 74.375,56.325 r90 bottom value=10K
R103 "Resistor" R0402 80.171,57.511 r90 bottom value=10K
R104 "Resistor" R0402 80.175,55.805 r270 bottom value=10K
R210 "Resistor" R0402 11.386,37.465 r270 top value=270R
R248 "Resistor" R0402 80.657,58.98 r0 bottom value=10K
R260 "Resistor" R0402 28.805,50.13 r270 bottom value=1K5
R261 "Resistor" R0402 29.78,50.13 r270 bottom value=1K5
R267 "" R0402 57.773,34.723 r180 bottom value=0R
R269 "" R0402 58.956,31.808 r90 top value=0R
R272 "Resistor" R0402 21.95,33.879 r0 bottom value=10K
R286 "" R0402 67.89,32.365 r90 bottom value=0R
TP21 "Test Point" TP_SMD_1MM 78.516,55.665 r90 bottom
U1 "STM32MP257FAK3" ICC_TFBGA424_14X14_P050_H1P20_CODE-B0A2 62.875,41.325 r0 top locked
U2 "MT53E1G32D2FW-046 WT:C" ICC_TFBGA200_10X14P5_P080_H1P05_PS0P3 85.26,41.29 r180 top locked
U26 "STPMIC25APQR" ICC_QFN56-EPAD_6P5X6P5_P040 28.5,43.8 r90 top
U37 "eMMC_THGBMTG5D1LBAIL" ICC_P-WFBGA153_13X11P5_P050 77.675,58.405 r0 top locked value=THGBMTG5D1LBAIL
X1 "XTAL_2_PINS" CRY_NX2012SA_2P 51.059,37.225 r270 top value=32.768KHz
X2 "XTAL_4_PINS" CRY_NX1612SA_4P 54.759,32.135 r180 top value=40MHz

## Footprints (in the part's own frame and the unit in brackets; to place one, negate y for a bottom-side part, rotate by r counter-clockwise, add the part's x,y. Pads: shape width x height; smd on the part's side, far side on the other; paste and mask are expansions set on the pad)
C0201_H0P5 [mm] "MCD-01534"
  rect 0.4x0.5 smd mask+0.05: 1(-0.3,0) 2(0.3,0)
  body extent -0.35,-0.2 0.35,0.2, height 0.55
C0201_MURATA_GRM033_H0P3 [mm] "GRM033R60J105ME11"
  rect 0.35x0.35 smd mask+0.05: 1(-0.275,0) 2(0.275,0)
  body extent -0.32,-0.17 0.32,0.17, height 0.33
C0402 [mm]
  rect 0.51x0.56 smd mask+0.05: 1(-0.45,0) 2(0.45,0)
  body extent -0.5,-0.3 0.5,0.3, height 0.4
C0603 [mm]
  rect 0.64x0.89 smd mask+0.05: 1(-0.7,0) 2(0.7,0)
  silkscreen extent -1.05,-0.55 1.02,0.55, body extent -0.9,-0.5 0.9,0.5, height 1.4
C0805 [mm]
  rect 0.9x1.4 smd mask+0.05: 1(-0.85,0) 2(0.85,0)
  silkscreen extent -1.3,-0.77 1.3,0.77, body extent -1.1,-0.7 1.1,0.7, height 1.35
CON_MOLEX_53047-0210 [mm]
  oval 1x1.3 hole 0.5 mask+0.05: 1(-0.625,0) 2(0.625,0)
  silkscreen extent -2.12,-1.15 2.13,2.05, body extent -2.12,-1.15 2.13,2.05, height 4.2
CPOL_TCJ-B_1210_H210 [mm] "MCD-01791"
  rect 1.35x2.8 smd mask+0.05: 1(-1.375,0) 2(1.375,0)
  silkscreen extent -2.33,-1.68 1.85,1.68, body extent -1.85,-1.5 1.85,1.5, height 2.11
CRY_NX1612SA_4P [mm] "MCD-02262"
  rect 0.75x0.6 smd mask+0.038: 1(-0.525,-0.375) 2(0.525,-0.375) 3(0.525,0.375) 4(-0.525,0.375)
  silkscreen extent -1.02,-0.8 0.03,0.6, body extent -0.8,-0.6 0.8,0.6, height 0.51
CRY_NX2012SA_2P [mm]
  rect 1x1.25 smd mask+0.05: 1(-0.75,0) 2(0.75,0)
  silkscreen extent -1.05,-0.75 1.05,0.75, body extent -1.05,-0.63 1.05,0.63, height 0.6
DIO_SOD323 [mm]
  rect 1.06x0.54 smd mask+0.05: 1(-1.07,0) 2(1.07,0)
  silkscreen extent -0.9,-0.72 0.9,0.72, body extent -1.3,-0.78 1.3,0.78, height 1.17
DIO_SOT23 [mm]
  rect 1x1.4 smd mask+0.05: 1(-0.95,-1.1) 2(0.95,-1.1) 3(0,1.1)
  silkscreen extent -1.63,-0.82 1.63,0.82, body extent -1.56,-1.25 1.56,1.25, height 1.1
ICC_P-WFBGA153_13X11P5_P050 [mm]
  round 0.23 smd mask+0.05: A1(-3.25,-3.25) A2(-3.25,-2.75) A3(-3.25,-2.25) A4(-3.25,-1.75) A5(-3.25,-1.25) A6(-3.25,-0.75) A7(-3.25,-0.25) A8(-3.25,0.25) A9(-3.25,0.75) A10(-3.25,1.25) A11(-3.25,1.75) A12(-3.25,2.25) A13(-3.25,2.75) A14(-3.25,3.25) B1(-2.75,-3.25) B2(-2.75,-2.75) B3(-2.75,-2.25) B4(-2.75,-1.75) B5(-2.75,-1.25) B6(-2.75,-0.75) B7(-2.75,-0.25) B8(-2.75,0.25) B9(-2.75,0.75) B10(-2.75,1.25) B11(-2.75,1.75) B12(-2.75,2.25) B13(-2.75,2.75) B14(-2.75,3.25) C1(-2.25,-3.25) C2(-2.25,-2.75) C3(-2.25,-2.25) C4(-2.25,-1.75) C5(-2.25,-1.25) C6(-2.25,-0.75) C7(-2.25,-0.25) C8(-2.25,0.25) C9(-2.25,0.75) C10(-2.25,1.25) C11(-2.25,1.75) C12(-2.25,2.25) C13(-2.25,2.75) C14(-2.25,3.25) D1(-1.75,-3.25) D2(-1.75,-2.75) D3(-1.75,-2.25) D4(-1.75,-1.75) D12(-1.75,2.25) D13(-1.75,2.75) D14(-1.75,3.25) E1(-1.25,-3.25) E2(-1.25,-2.75) E3(-1.25,-2.25) E5(-1.25,-1.25) E6(-1.25,-0.75) E7(-1.25,-0.25) E8(-1.25,0.25) E9(-1.25,0.75) E10(-1.25,1.25) E12(-1.25,2.25) E13(-1.25,2.75) E14(-1.25,3.25) F1(-0.75,-3.25) F2(-0.75,-2.75) F3(-0.75,-2.25) F5(-0.75,-1.25) F10(-0.75,1.25) F12(-0.75,2.25) F13(-0.75,2.75) F14(-0.75,3.25) G1(-0.25,-3.25) G2(-0.25,-2.75) G3(-0.25,-2.25) G5(-0.25,-1.25) G10(-0.25,1.25) G12(-0.25,2.25) G13(-0.25,2.75) G14(-0.25,3.25) H1(0.25,-3.25) H2(0.25,-2.75) H3(0.25,-2.25) H5(0.25,-1.25) H10(0.25,1.25) H12(0.25,2.25) H13(0.25,2.75) H14(0.25,3.25) J1(0.75,-3.25) J2(0.75,-2.75) J3(0.75,-2.25) J5(0.75,-1.25) J10(0.75,1.25) J12(0.75,2.25) J13(0.75,2.75) J14(0.75,3.25) K1(1.25,-3.25) K2(1.25,-2.75) K3(1.25,-2.25) K5(1.25,-1.25) K6(1.25,-0.75) K7(1.25,-0.25) K8(1.25,0.25) K9(1.25,0.75) K10(1.25,1.25) K12(1.25,2.25) K13(1.25,2.75) K14(1.25,3.25) L1(1.75,-3.25) L2(1.75,-2.75) L3(1.75,-2.25) L12(1.75,2.25) L13(1.75,2.75) L14(1.75,3.25) M1(2.25,-3.25) M2(2.25,-2.75) M3(2.25,-2.25) M4(2.25,-1.75) M5(2.25,-1.25) M6(2.25,-0.75) M7(2.25,-0.25) M8(2.25,0.25) M9(2.25,0.75) M10(2.25,1.25) M11(2.25,1.75) M12(2.25,2.25) M13(2.25,2.75) M14(2.25,3.25) N1(2.75,-3.25) N2(2.75,-2.75) N3(2.75,-2.25) N4(2.75,-1.75) N5(2.75,-1.25) N6(2.75,-0.75) N7(2.75,-0.25) N8(2.75,0.25) N9(2.75,0.75) N10(2.75,1.25) N11(2.75,1.75) N12(2.75,2.25) N13(2.75,2.75) N14(2.75,3.25) P1(3.25,-3.25) P2(3.25,-2.75) P3(3.25,-2.25) P4(3.25,-1.75) P5(3.25,-1.25) P6(3.25,-0.75) P7(3.25,-0.25) P8(3.25,0.25) P9(3.25,0.75) P10(3.25,1.25) P11(3.25,1.75) P12(3.25,2.25) P13(3.25,2.75) P14(3.25,3.25)
  silkscreen extent -6.78,-6.02 6.63,5.87, body extent -6.55,-5.8 6.55,5.8, height 1
ICC_QFN56-EPAD_6P5X6P5_P040 [mm] "MCD-03000"
  rect 0.55x0.21 smd mask+0.05: 1(-3.245,2.6) 14(-3.245,-2.6) 29(3.245,-2.6) 42(3.245,2.6)
  rect 0.7x0.21 smd mask+0.05: 2(-3.17,2.2) 3(-3.17,1.8) 4(-3.17,1.4) 5(-3.17,1) 6(-3.17,0.6) 7(-3.17,0.2) 8(-3.17,-0.2) 9(-3.17,-0.6) 10(-3.17,-1) 11(-3.17,-1.4) 12(-3.17,-1.8) 13(-3.17,-2.2) 30(3.17,-2.2) 31(3.17,-1.8) 32(3.17,-1.4) 33(3.17,-1) 34(3.17,-0.6) 35(3.17,-0.2) 36(3.17,0.2) 37(3.17,0.6) 38(3.17,1) 39(3.17,1.4) 40(3.17,1.8) 41(3.17,2.2)
  rect 0.21x0.55 smd mask+0.05: 15(-2.6,-3.245) 28(2.6,-3.245) 43(2.6,3.245) 56(-2.6,3.245)
  rect 0.21x0.7 smd mask+0.05: 16(-2.2,-3.17) 17(-1.8,-3.17) 18(-1.4,-3.17) 19(-1,-3.17) 20(-0.6,-3.17) 21(-0.2,-3.17) 22(0.2,-3.17) 23(0.6,-3.17) 24(1,-3.17) 25(1.4,-3.17) 26(1.8,-3.17) 27(2.2,-3.17) 44(2.2,3.17) 45(1.8,3.17) 46(1.4,3.17) 47(1,3.17) 48(0.6,3.17) 49(0.2,3.17) 50(-0.2,3.17) 51(-0.6,3.17) 52(-1,3.17) 53(-1.4,3.17) 54(-1.8,3.17) 55(-2.2,3.17)
  rect 4.7x4.7 smd mask+0.05: 57(0,0)
  Top Layer region: -2.495,-2.97 -2.495,-2.82 -2.555,-2.82 -2.705,-2.97
  Top Layer region: 2.495,2.97 2.495,2.82 2.555,2.82 2.705,2.97
  Top Layer region: 2.97,2.495 2.82,2.495 2.82,2.555 2.97,2.705
  Top Layer region: 2.495,-2.97 2.495,-2.82 2.555,-2.82 2.705,-2.97
  Top Layer region: 2.97,-2.495 2.82,-2.495 2.82,-2.555 2.97,-2.705
  Top Layer region: -2.495,2.97 -2.495,2.82 -2.555,2.82 -2.705,2.97
  Top Layer region: -2.97,-2.495 -2.82,-2.495 -2.82,-2.555 -2.97,-2.705
  Top Layer region: -2.97,2.495 -2.82,2.495 -2.82,2.555 -2.97,2.705
  silkscreen extent -3.44,3 -3.01,3.42, body extent -3.25,-3.25 3.25,3.25, height 0.91
ICC_TFBGA200_10X14P5_P080_H1P05_PS0P3 [mm] "MCD-04012"
  round 0.3 smd mask+0.05: A1(-4.4,6.825) A2(-3.6,6.825) A3(-2.8,6.825) A4(-2,6.825) A5(-1.2,6.825) A8(1.2,6.825) A9(2,6.825) A10(2.8,6.825) A11(3.6,6.825) A12(4.4,6.825) AA1(-4.4,-6.175) AA2(-3.6,-6.175) AA3(-2.8,-6.175) AA4(-2,-6.175) AA5(-1.2,-6.175) AA8(1.2,-6.175) AA9(2,-6.175) AA10(2.8,-6.175) AA11(3.6,-6.175) AA12(4.4,-6.175) AB1(-4.4,-6.825) AB2(-3.6,-6.825) AB3(-2.8,-6.825) AB4(-2,-6.825) AB5(-1.2,-6.825) AB8(1.2,-6.825) AB9(2,-6.825) AB10(2.8,-6.825) AB11(3.6,-6.825) AB12(4.4,-6.825) B1(-4.4,6.175) B2(-3.6,6.175) B3(-2.8,6.175) B4(-2,6.175) B5(-1.2,6.175) B8(1.2,6.175) B9(2,6.175) B10(2.8,6.175) B11(3.6,6.175) B12(4.4,6.175) C1(-4.4,5.525) C2(-3.6,5.525) C3(-2.8,5.525) C4(-2,5.525) C5(-1.2,5.525) C8(1.2,5.525) C9(2,5.525) C10(2.8,5.525) C11(3.6,5.525) C12(4.4,5.525) D1(-4.4,4.875) D2(-3.6,4.875) D3(-2.8,4.875) D4(-2,4.875) D5(-1.2,4.875) D8(1.2,4.875) D9(2,4.875) D10(2.8,4.875) D11(3.6,4.875) D12(4.4,4.875) E1(-4.4,4.225) E2(-3.6,4.225) E3(-2.8,4.225) E4(-2,4.225) E5(-1.2,4.225) E8(1.2,4.225) E9(2,4.225) E10(2.8,4.225) E11(3.6,4.225) E12(4.4,4.225) F1(-4.4,3.575) F2(-3.6,3.575) F3(-2.8,3.575) F4(-2,3.575) F5(-1.2,3.575) F8(1.2,3.575) F9(2,3.575) F10(2.8,3.575) F11(3.6,3.575) F12(4.4,3.575) G1(-4.4,2.925) G2(-3.6,2.925) G3(-2.8,2.925) G4(-2,2.925) G5(-1.2,2.925) G8(1.2,2.925) G9(2,2.925) G10(2.8,2.925) G11(3.6,2.925) G12(4.4,2.925) H1(-4.4,2.275) H2(-3.6,2.275) H3(-2.8,2.275) H4(-2,2.275) H5(-1.2,2.275) H8(1.2,2.275) H9(2,2.275) H10(2.8,2.275) H11(3.6,2.275) H12(4.4,2.275) J1(-4.4,1.625) J2(-3.6,1.625) J3(-2.8,1.625) J4(-2,1.625) J5(-1.2,1.625) J8(1.2,1.625) J9(2,1.625) J10(2.8,1.625) J11(3.6,1.625) J12(4.4,1.625) K1(-4.4,0.975) K2(-3.6,0.975) K3(-2.8,0.975) K4(-2,0.975) K5(-1.2,0.975) K8(1.2,0.975) K9(2,0.975) K10(2.8,0.975) K11(3.6,0.975) K12(4.4,0.975) N1(-4.4,-0.975) N2(-3.6,-0.975) N3(-2.8,-0.975) N4(-2,-0.975) N5(-1.2,-0.975) N8(1.2,-0.975) N9(2,-0.975) N10(2.8,-0.975) N11(3.6,-0.975) N12(4.4,-0.975) P1(-4.4,-1.625) P2(-3.6,-1.625) P3(-2.8,-1.625) P4(-2,-1.625) P5(-1.2,-1.625) P8(1.2,-1.625) P9(2,-1.625) P10(2.8,-1.625) P11(3.6,-1.625) P12(4.4,-1.625) R1(-4.4,-2.275) R2(-3.6,-2.275) R3(-2.8,-2.275) R4(-2,-2.275) R5(-1.2,-2.275) R8(1.2,-2.275) R9(2,-2.275) R10(2.8,-2.275) R11(3.6,-2.275) R12(4.4,-2.275) T1(-4.4,-2.925) T2(-3.6,-2.925) T3(-2.8,-2.925) T4(-2,-2.925) T5(-1.2,-2.925) T8(1.2,-2.925) T9(2,-2.925) T10(2.8,-2.925) T11(3.6,-2.925) T12(4.4,-2.925) U1(-4.4,-3.575) U2(-3.6,-3.575) U3(-2.8,-3.575) U4(-2,-3.575) U5(-1.2,-3.575) U8(1.2,-3.575) U9(2,-3.575) U10(2.8,-3.575) U11(3.6,-3.575) U12(4.4,-3.575) V1(-4.4,-4.225) V2(-3.6,-4.225) V3(-2.8,-4.225) V4(-2,-4.225) V5(-1.2,-4.225) V8(1.2,-4.225) V9(2,-4.225) V10(2.8,-4.225) V11(3.6,-4.225) V12(4.4,-4.225) W1(-4.4,-4.875) W2(-3.6,-4.875) W3(-2.8,-4.875) W4(-2,-4.875) W5(-1.2,-4.875) W8(1.2,-4.875) W9(2,-4.875) W10(2.8,-4.875) W11(3.6,-4.875) W12(4.4,-4.875) Y1(-4.4,-5.525) Y2(-3.6,-5.525) Y3(-2.8,-5.525) Y4(-2,-5.525) Y5(-1.2,-5.525) Y8(1.2,-5.525) Y9(2,-5.525) Y10(2.8,-5.525) Y11(3.6,-5.525) Y12(4.4,-5.525)
  silkscreen extent -5.2,-7.3 5.05,7.45, body extent -5.05,-7.3 5.05,7.3, height 1.06
ICC_TFBGA424_14X14_P050_H1P20_CODE-B0A2 [mm] "MCD_03375"
  round 0.23 smd paste+0.025 mask+0.05: 1A1(-2.75,2.75) 1A3(-1.75,2.75) 1A5(-0.75,2.75) 1A7(0.25,2.75) 1A9(1.25,2.75) 1A11(2.25,2.75) 1B2(-2.25,2.25) 1B4(-1.25,2.25) 1B6(-0.25,2.25) 1B8(0.75,2.25) 1B10(1.75,2.25) 1B12(2.75,2.25) 1C1(-2.75,1.75) 1C3(-1.75,1.75) 1C5(-0.75,1.75) 1C7(0.25,1.75) 1C9(1.25,1.75) 1C11(2.25,1.75) 1D2(-2.25,1.25) 1D4(-1.25,1.25) 1D6(-0.25,1.25) 1D8(0.75,1.25) 1D10(1.75,1.25) 1D12(2.75,1.25) 1E1(-2.75,0.75) 1E3(-1.75,0.75) 1E5(-0.75,0.75) 1E7(0.25,0.75) 1E9(1.25,0.75) 1E11(2.25,0.75) 1F2(-2.25,0.25) 1F4(-1.25,0.25) 1F6(-0.25,0.25) 1F8(0.75,0.25) 1F10(1.75,0.25) 1F12(2.75,0.25) 1G1(-2.75,-0.25) 1G3(-1.75,-0.25) 1G5(-0.75,-0.25) 1G7(0.25,-0.25) 1G9(1.25,-0.25) 1G11(2.25,-0.25) 1H2(-2.25,-0.75) 1H4(-1.25,-0.75) 1H6(-0.25,-0.75) 1H8(0.75,-0.75) 1H10(1.75,-0.75) 1H12(2.75,-0.75) 1J1(-2.75,-1.25) 1J3(-1.75,-1.25) 1J5(-0.75,-1.25) 1J7(0.25,-1.25) 1J9(1.25,-1.25) 1J11(2.25,-1.25) 1K2(-2.25,-1.75) 1K4(-1.25,-1.75) 1K6(-0.25,-1.75) 1K8(0.75,-1.75) 1K10(1.75,-1.75) 1K12(2.75,-1.75) 1L1(-2.75,-2.25) 1L3(-1.75,-2.25) 1L5(-0.75,-2.25) 1L7(0.25,-2.25) 1L9(1.25,-2.25) 1L11(2.25,-2.25) 1M2(-2.25,-2.75) 1M4(-1.25,-2.75) 1M6(-0.25,-2.75) 1M8(0.75,-2.75) 1M10(1.75,-2.75) 1M12(2.75,-2.75) A1(-6.5,6.5) A2(-6,6.5) A3(-5.5,6.5) A6(-4,6.5) A7(-3.5,6.5) A10(-2,6.5) A11(-1.5,6.5) A14(0,6.5) A15(0.5,6.5) A18(2,6.5) A19(2.5,6.5) A22(4,6.5) A23(4.5,6.5) A26(6,6.5) A27(6.5,6.5) AA1(-6.5,-3.5) AA2(-6,-3.5) AA3(-5.5,-3.5) AA5(-4.5,-3.5) AA7(-3.5,-3.5) AA9(-2.5,-3.5) AA11(-1.5,-3.5) AA13(-0.5,-3.5) AA15(0.5,-3.5) AA17(1.5,-3.5) AA19(2.5,-3.5) AA21(3.5,-3.5) AA23(4.5,-3.5) AA25(5.5,-3.5) AA26(6,-3.5) AB1(-6.5,-4) AB2(-6,-4) AB3(-5.5,-4) AB4(-5,-4) AB6(-4,-4) AB8(-3,-4) AB10(-2,-4) AB12(-1,-4) AB14(0,-4) AB16(1,-4) AB18(2,-4) AB20(3,-4) AB22(4,-4) AB24(5,-4) AB25(5.5,-4) AB26(6,-4) AB27(6.5,-4) AC2(-6,-4.5) AC3(-5.5,-4.5) AC5(-4.5,-4.5) AC7(-3.5,-4.5) AC9(-2.5,-4.5) AC11(-1.5,-4.5) AC13(-0.5,-4.5) AC15(0.5,-4.5) AC17(1.5,-4.5) AC19(2.5,-4.5) AC21(3.5,-4.5) AC23(4.5,-4.5) AC25(5.5,-4.5) AC26(6,-4.5) AC27(6.5,-4.5) AD3(-5.5,-5) AD4(-5,-5) AD6(-4,-5) AD8(-3,-5) AD10(-2,-5) AD12(-1,-5) AD14(0,-5) AD16(1,-5) AD18(2,-5) AD20(3,-5) AD22(4,-5) AD24(5,-5) AD25(5.5,-5) AE1(-6.5,-5.5) AE2(-6,-5.5) AE3(-5.5,-5.5) AE4(-5,-5.5) AE5(-4.5,-5.5) AE6(-4,-5.5) AE7(-3.5,-5.5) AE8(-3,-5.5) AE9(-2.5,-5.5) AE10(-2,-5.5) AE11(-1.5,-5.5) AE12(-1,-5.5) AE13(-0.5,-5.5) AE14(0,-5.5) AE15(0.5,-5.5) AE16(1,-5.5) AE17(1.5,-5.5) AE18(2,-5.5) AE19(2.5,-5.5) AE20(3,-5.5) AE21(3.5,-5.5) AE22(4,-5.5) AE23(4.5,-5.5) AE24(5,-5.5) AE25(5.5,-5.5) AE26(6,-5.5) AF1(-6.5,-6) AF2(-6,-6) AF3(-5.5,-6) AF5(-4.5,-6) AF6(-4,-6) AF7(-3.5,-6) AF9(-2.5,-6) AF10(-2,-6) AF11(-1.5,-6) AF13(-0.5,-6) AF14(0,-6) AF15(0.5,-6) AF17(1.5,-6) AF18(2,-6) AF19(2.5,-6) AF21(3.5,-6) AF22(4,-6) AF23(4.5,-6) AF25(5.5,-6) AF26(6,-6) AF27(6.5,-6) AG1(-6.5,-6.5) AG2(-6,-6.5) AG5(-4.5,-6.5) AG6(-4,-6.5) AG9(-2.5,-6.5) AG10(-2,-6.5) AG13(-0.5,-6.5) AG14(0,-6.5) AG17(1.5,-6.5) AG18(2,-6.5) AG21(3.5,-6.5) AG22(4,-6.5) AG25(5.5,-6.5) AG26(6,-6.5) AG27(6.5,-6.5) B1(-6.5,6) B2(-6,6) B3(-5.5,6) B5(-4.5,6) B6(-4,6) B7(-3.5,6) B9(-2.5,6) B10(-2,6) B11(-1.5,6) B13(-0.5,6) B14(0,6) B15(0.5,6) B17(1.5,6) B18(2,6) B19(2.5,6) B21(3.5,6) B22(4,6) B23(4.5,6) B25(5.5,6) B26(6,6) B27(6.5,6) C2(-6,5.5) C3(-5.5,5.5) C4(-5,5.5) C5(-4.5,5.5) C6(-4,5.5) C7(-3.5,5.5) C8(-3,5.5) C9(-2.5,5.5) C10(-2,5.5) C11(-1.5,5.5) C12(-1,5.5) C13(-0.5,5.5) C14(0,5.5) C15(0.5,5.5) C16(1,5.5) C17(1.5,5.5) C18(2,5.5) C19(2.5,5.5) C20(3,5.5) C21(3.5,5.5) C22(4,5.5) C23(4.5,5.5) C24(5,5.5) C25(5.5,5.5) C26(6,5.5) C27(6.5,5.5) D3(-5.5,5) D4(-5,5) D6(-4,5) D8(-3,5) D10(-2,5) D12(-1,5) D14(0,5) D16(1,5) D18(2,5) D20(3,5) D22(4,5) D24(5,5) D25(5.5,5) E1(-6.5,4.5) E2(-6,4.5) E3(-5.5,4.5) E5(-4.5,4.5) E7(-3.5,4.5) E9(-2.5,4.5) E11(-1.5,4.5) E13(-0.5,4.5) E15(0.5,4.5) E17(1.5,4.5) E19(2.5,4.5) E21(3.5,4.5) E23(4.5,4.5) E25(5.5,4.5) E26(6,4.5) F1(-6.5,4) F2(-6,4) F3(-5.5,4) F4(-5,4) F6(-4,4) F8(-3,4) F10(-2,4) F12(-1,4) F14(0,4) F16(1,4) F18(2,4) F20(3,4) F22(4,4) F24(5,4) F25(5.5,4) F26(6,4) F27(6.5,4) G2(-6,3.5) G3(-5.5,3.5) G5(-4.5,3.5) G7(-3.5,3.5) G9(-2.5,3.5) G11(-1.5,3.5) G13(-0.5,3.5) G15(0.5,3.5) G17(1.5,3.5) G19(2.5,3.5) G21(3.5,3.5) G23(4.5,3.5) G25(5.5,3.5) G26(6,3.5) G27(6.5,3.5) H3(-5.5,3) H4(-5,3) H6(-4,3) H22(4,3) H24(5,3) H25(5.5,3) J1(-6.5,2.5) J2(-6,2.5) J3(-5.5,2.5) J5(-4.5,2.5) J7(-3.5,2.5) J21(3.5,2.5) J23(4.5,2.5) J25(5.5,2.5) J26(6,2.5) K1(-6.5,2) K2(-6,2) K3(-5.5,2) K4(-5,2) K6(-4,2) K22(4,2) K24(5,2) K25(5.5,2) K26(6,2) K27(6.5,2) L2(-6,1.5) L3(-5.5,1.5) L5(-4.5,1.5) L7(-3.5,1.5) L21(3.5,1.5) L23(4.5,1.5) L25(5.5,1.5) L26(6,1.5) L27(6.5,1.5) M3(-5.5,1) M4(-5,1) M6(-4,1) M22(4,1) M24(5,1) M25(5.5,1) N1(-6.5,0.5) N2(-6,0.5) N3(-5.5,0.5) N5(-4.5,0.5) N7(-3.5,0.5) N21(3.5,0.5) N23(4.5,0.5) N25(5.5,0.5) N26(6,0.5) P1(-6.5,0) P2(-6,0) P3(-5.5,0) P4(-5,0) P6(-4,0) P22(4,0) P24(5,0) P25(5.5,0) P26(6,0) P27(6.5,0) R2(-6,-0.5) R3(-5.5,-0.5) R5(-4.5,-0.5) R7(-3.5,-0.5) R21(3.5,-0.5) R23(4.5,-0.5) R25(5.5,-0.5) R26(6,-0.5) R27(6.5,-0.5) T3(-5.5,-1) T4(-5,-1) T6(-4,-1) T22(4,-1) T24(5,-1) T25(5.5,-1) U1(-6.5,-1.5) U2(-6,-1.5) U3(-5.5,-1.5) U5(-4.5,-1.5) U7(-3.5,-1.5) U21(3.5,-1.5) U23(4.5,-1.5) U25(5.5,-1.5) U26(6,-1.5) V1(-6.5,-2) V2(-6,-2) V3(-5.5,-2) V4(-5,-2) V6(-4,-2) V22(4,-2) V24(5,-2) V25(5.5,-2) V26(6,-2) V27(6.5,-2) W2(-6,-2.5) W3(-5.5,-2.5) W5(-4.5,-2.5) W7(-3.5,-2.5) W21(3.5,-2.5) W23(4.5,-2.5) W25(5.5,-2.5) W26(6,-2.5) W27(6.5,-2.5) Y3(-5.5,-3) Y4(-5,-3) Y6(-4,-3) Y22(4,-3) Y24(5,-3) Y25(5.5,-3)
  silkscreen extent -7.17,-7 7,7.17, body extent -7,-7 7,7, height 1.21
IND_2016_MURATA_LQM2MPN2R2NG0 [mm]
  rect 0.8x1.8 smd mask+0.05: 1(-0.8,0) 2(0.8,0)
  silkscreen extent -0.28,-0.87 0.28,0.87, body extent -1.07,-0.87 1.08,0.87, height 1
IND_2520_TOKO_DFE252012P [mm]
  rect 0.8x2 smd mask+0.05: 1(-1,0) 2(1,0)
  silkscreen extent -1.35,-1.12 1.35,1.12, body extent -1.35,-1.1 1.35,1.1, height 2
LED_0603_OSRAM_LG-Q396-PS-35_GREEN_1A2K_H0P4 [mm]
  rect 0.8x0.8 smd mask+0.05: 1(-0.75,0) 2(0.75,0)
  silkscreen extent -0.85,-0.53 1.28,0.53, body extent -0.85,-0.45 0.85,0.45, height 0.6
LINK200 [mm]
  rect 0.2x0.35 smd paste-10 mask+0.05: 1(0,-0.225) 2(0,0.225)
R0201_H0P23 [mm] "MCD-00702"
  rect 0.4x0.5 smd mask+0.05: 1(-0.3,0) 2(0.3,0)
  body extent -0.32,-0.17 0.32,0.17, height 0.26
R0402 [mm]
  rect 0.51x0.7 smd mask+0.05: 1(-0.45,0) 2(0.45,0)
  body extent -0.52,-0.3 0.52,0.3, height 0.4
R0603 [mm]
  rect 0.64x1 smd mask+0.05: 1(-0.7,0) 2(0.7,0)
  silkscreen extent -1.05,-0.58 1.05,0.58, body extent -0.9,-0.5 0.9,0.5, height 0.56
SWI_WE_434121025816 [mm] "MCD-03492"
  rect 1.5x1.4 smd: 1(-3.25,0) 2(3.25,0)
  silkscreen extent -3,-1.95 3,1.95, body extent -3.65,-1.95 3.65,1.95, height 2.51
TP_SMD_1MM [mm]
  round 1 smd paste-10 mask+0.05: 1(0,0)
  silkscreen extent -0.7,-0.7 0.7,0.7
